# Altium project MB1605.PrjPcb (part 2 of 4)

## Sheet Power_PMIC.SchDoc: Power PMIC
size A3; Date: Not used; ApprovedBy: Not used; CheckedBy: Not used; Author: Not used; CompanyName: STMicroelectronics; DrawnBy: Not used; Engineer: Not used; Organization: Not used; Address1: Not used; Address2: Not used; Address3: Not used; Address4: Not used; DocumentNumber: Not used; Revision: Not used; SheetNumber: 4; SheetTotal: 18
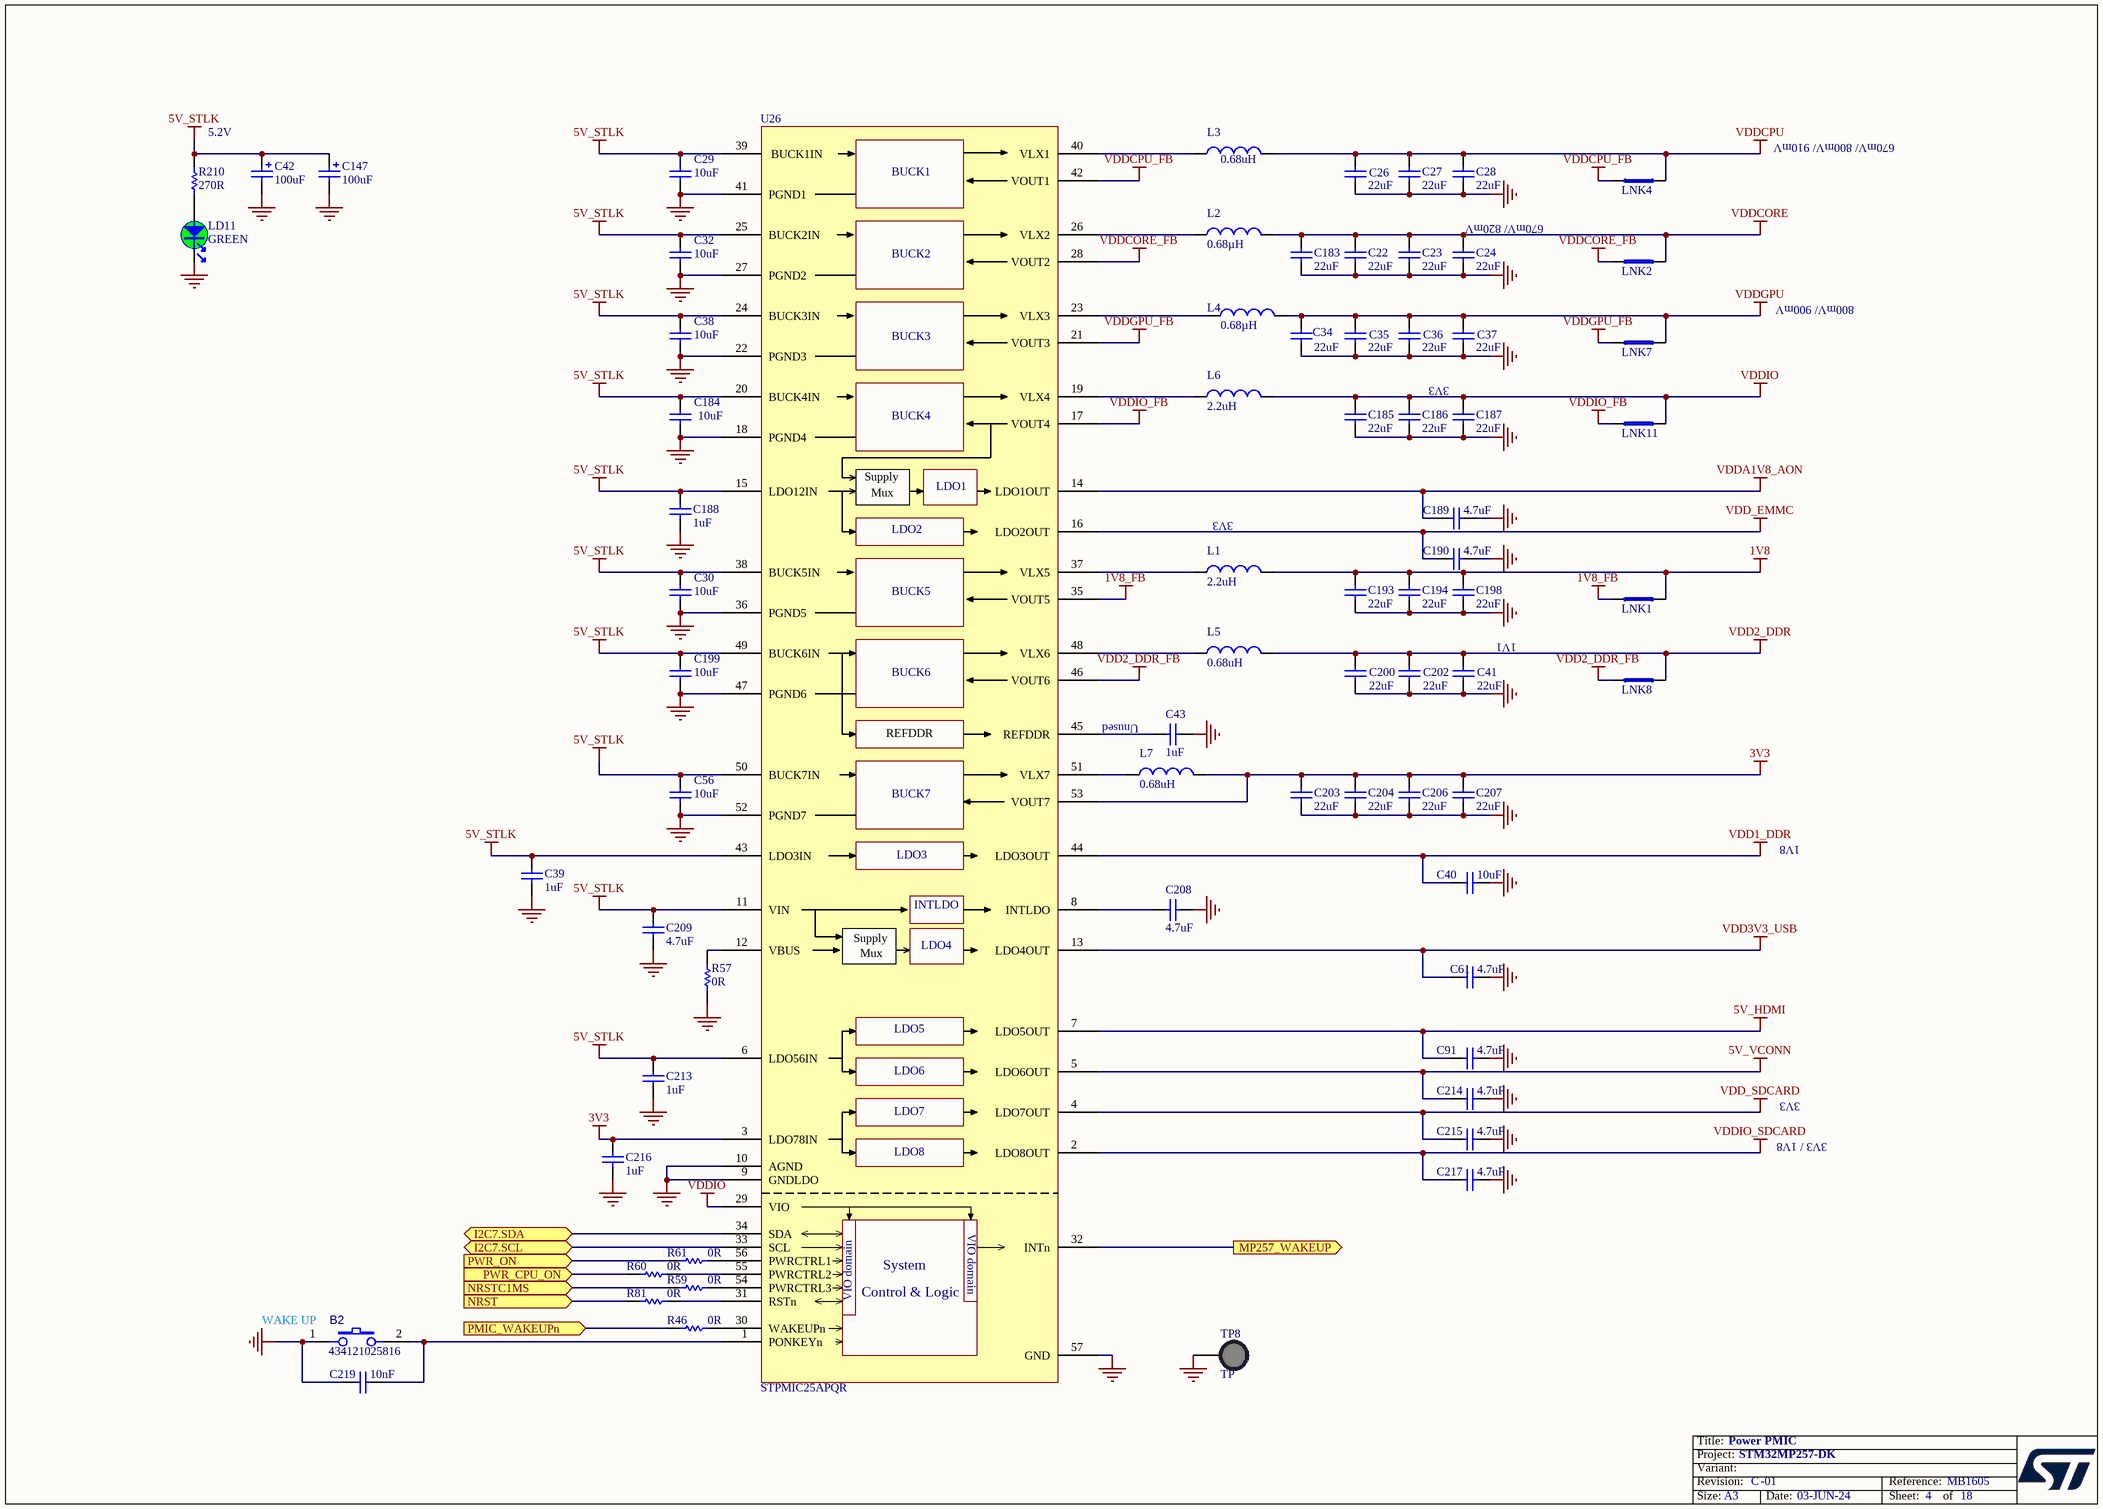
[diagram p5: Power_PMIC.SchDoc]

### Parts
B2  value 434121025816  [SWI_WE_434121025816]  (hidden comment: SW_PUSH_SMD_2P)
C22  value 22uF  [C0603]  (hidden comment: Capacitor)
C23  value 22uF  [C0603]  (hidden comment: Capacitor)
C24  value 22uF  [C0603]  (hidden comment: Capacitor)
C26  value 22uF  [C0603]  (hidden comment: Capacitor)
C27  value 22uF  [C0603]  (hidden comment: Capacitor)
C28  value 22uF  [C0603]  (hidden comment: Capacitor)
C29  value 10uF  [C0603]  (hidden comment: Capacitor)
C30  value 10uF  [C0603]  (hidden comment: Capacitor)
C32  value 10uF  [C0603]  (hidden comment: Capacitor)
C34  value 22uF  [C0603]  (hidden comment: Capacitor)
C35  value 22uF  [C0603]  (hidden comment: Capacitor)
C36  value 22uF  [C0603]  (hidden comment: Capacitor)
C37  value 22uF  [C0603]  (hidden comment: Capacitor)
C38  value 10uF  [C0603]  (hidden comment: Capacitor)
C39  value 1uF  [C0402]  (hidden comment: Capacitor)
C40  value 10uF  [C0402]  (hidden comment: Capacitor)
C41  value 22uF  [C0603]  (hidden comment: Capacitor)
C42  value 100uF  [CPOL_TCJ-B_1210_H210]  (hidden comment: Cap_POL_TANA)
C43  value 1uF  [C0402]  (hidden comment: Capacitor)
C56  value 10uF  [C0603]  (hidden comment: Capacitor)
C61  value 4.7uF  [C0402]  (hidden comment: Capacitor)
C91  value 4.7uF  [C0402]  (hidden comment: Capacitor)
C147  value 100uF  [CPOL_TCJ-B_1210_H210]  (hidden comment: Cap_POL_TANA)
C183  value 22uF  [C0603]  (hidden comment: Capacitor)
C184  value 10uF  [C0603]  (hidden comment: Capacitor)
C185  value 22uF  [C0805]  (hidden comment: Capacitor)
C186  value 22uF  [C0805]  (hidden comment: Capacitor)
C187  value 22uF  [C0805]  (hidden comment: Capacitor)
C188  value 1uF  [C0402]  (hidden comment: Capacitor)
C189  value 4.7uF  [C0402]  (hidden comment: Capacitor)
C190  value 4.7uF  [C0402]  (hidden comment: Capacitor)
C193  value 22uF  [C0805]  (hidden comment: Capacitor)
C194  value 22uF  [C0805]  (hidden comment: Capacitor)
C198  value 22uF  [C0805]  (hidden comment: Capacitor)
C199  value 10uF  [C0603]  (hidden comment: Capacitor)
C200  value 22uF  [C0603]  (hidden comment: Capacitor)
C202  value 22uF  [C0603]  (hidden comment: Capacitor)
C203  value 22uF  [C0805]  (hidden comment: Capacitor)
C204  value 22uF  [C0805]  (hidden comment: Capacitor)
C206  value 22uF  [C0805]  (hidden comment: Capacitor)
C207  value 22uF  [C0805]  (hidden comment: Capacitor)
C208  value 4.7uF  [C0402]  (hidden comment: Capacitor)
C209  value 4.7uF  [C0402]  (hidden comment: Capacitor)
C213  value 1uF  [C0402]  (hidden comment: Capacitor)
C214  value 4.7uF  [C0402]  (hidden comment: Capacitor)
C215  value 4.7uF  [C0402]  (hidden comment: Capacitor)
C216  value 1uF  [C0402]  (hidden comment: Capacitor)
C217  value 4.7uF  [C0402]  (hidden comment: Capacitor)
C219  value 10nF  [C0402]  (hidden comment: Capacitor)
L1  value 2.2uH  [IND_2016_MURATA_LQM2MPN2R2NG0]  (hidden comment: Inductor)
L2  value 0.68µH  [IND_2520_TOKO_DFE252012P]  (hidden comment: Inductor)
L3  value 0.68uH  [IND_2016_MURATA_LQM2MPN2R2NG0]  (hidden comment: Inductor)
L4  value 0.68µH  [IND_2520_TOKO_DFE252012P]  (hidden comment: Inductor)
L5  value 0.68uH  [IND_2016_MURATA_LQM2MPN2R2NG0]  (hidden comment: Inductor)
L6  value 2.2uH  [IND_2016_MURATA_LQM2MPN2R2NG0]  (hidden comment: Inductor)
L7  value 0.68uH  [IND_2016_MURATA_LQM2MPN2R2NG0]  (hidden comment: Inductor)
LD11  value GREEN  [LED_0603_OSRAM_LG-Q396-PS-35_GREEN_1A2K_H0P4]  (hidden comment: LED_green)
LNK1  link_200  [LINK200]  (value not drawn)  (no BOM)
LNK2  link_200  [LINK200]  (value not drawn)  (no BOM)
LNK4  link_200  [LINK200]  (value not drawn)  (no BOM)
LNK7  link_200  [LINK200]  (value not drawn)  (no BOM)
LNK8  link_200  [LINK200]  (value not drawn)  (no BOM)
LNK11  link_200  [LINK200]  (value not drawn)  (no BOM)
R46  value 0R  [R0402]
R57  value 0R  [R0402]
R59  value 0R  [R0402]
R60  value 0R  [R0402]
R61  value 0R  [R0402]
R81  value 0R  [R0402]
R210  value 270R  [R0402]  (hidden comment: Resistor)
TP8  value TP  [TP_PTH-1P02MM_TEST-TERMINAL_RS_101-2391_BLACK]  (hidden comment: Test_pin_conn_black)
U26  STPMIC25APQR  [ICC_QFN56-EPAD_6P5X6P5_P040]

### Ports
I2C7.SCL (bidir), I2C7.SDA (bidir), MP257_WAKEUP (out), NRST (in), NRSTC1MS (in), PMIC_WAKEUPn (in), PWR_CPU_ON (in), PWR_ON (in)

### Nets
1V8: C193.2 C194.2 C198.2 L1.2 LNK1.2
1V8_FB: LNK1.1 U26.35(VOUT5)
3V3: C203.2 C204.2 C206.2 C207.2 C216.2 L7.2 U26.3(LDO78IN) U26.53(VOUT7)
5V_HDMI: C91.1 U26.7(LDO5OUT)
5V_STLK: C29.2 C30.2 C32.2 C38.2 C39.2 C42.1 C56.2 C147.1 C184.2 C188.2 C199.2 C209.2 C213.2 R210.1 U26.6(LDO56IN) U26.11(VIN) U26.15(LDO12IN) U26.20(BUCK4IN) U26.24(BUCK3IN) U26.25(BUCK2IN) U26.38(BUCK5IN) U26.39(BUCK1IN) U26.43(LDO3IN) U26.49(BUCK6IN) U26.50(BUCK7IN)
5V_VCONN: C214.1 U26.5(LDO6OUT)
GND: B2.1 C22.1 C23.1 C24.1 C26.1 C27.1 C28.1 C29.1 C30.1 C32.1 C34.1 C35.1 C36.1 C37.1 C38.1 C39.1 C40.1 C41.1 C42.2 C43.1 C56.1 C61.1 C91.2 C147.2 C183.1 C184.1 C185.1 C186.1 C187.1 C188.1 C189.1 C190.2 C193.1 C194.1 C198.1 C199.1 C200.1 C202.1 C203.1 C204.1 C206.1 C207.1 C208.2 C209.1 C213.1 C214.2 C215.2 C216.1 C217.2 C219.1 LD11.2 R57.1 TP8.1 U26.9(GNDLDO) U26.10(AGND) U26.18(PGND4) U26.22(PGND3) U26.27(PGND2) U26.36(PGND5) U26.41(PGND1) U26.47(PGND6) U26.52(PGND7) U26.57(GND)
VDD1_DDR: C40.2 U26.44(LDO3OUT)
VDD2_DDR: C41.2 C200.2 C202.2 L5.2 LNK8.2
VDD2_DDR_FB: LNK8.1 U26.46(VOUT6)
VDD3V3_USB: C61.2 U26.13(LDO4OUT)
VDD_EMMC: C190.1 U26.16(LDO2OUT)
VDD_SDCARD: C215.1 U26.4(LDO7OUT)
VDDA1V8_AON: C189.2 U26.14(LDO1OUT)
VDDCORE: C22.2 C23.2 C24.2 C183.2 L2.2 LNK2.2
VDDCORE_FB: LNK2.1 U26.28(VOUT2)
VDDCPU: C26.2 C27.2 C28.2 L3.2 LNK4.1
VDDCPU_FB: LNK4.2 U26.42(VOUT1)
VDDGPU: C34.2 C35.2 C36.2 C37.2 L4.2 LNK7.2
VDDGPU_FB: LNK7.1 U26.21(VOUT3)
VDDIO: C185.2 C186.2 C187.2 L6.2 LNK11.2 U26.29(VIO)
VDDIO_FB: LNK11.1 U26.17(VOUT4)
VDDIO_SDCARD: C217.1 U26.2(LDO8OUT)
I2C7.SCL: U26.33(SCL) ; port I2C7.SCL
I2C7.SDA: U26.34(SDA) ; port I2C7.SDA
MP257_WAKEUP: U26.32(INTn) ; port MP257_WAKEUP
NRST: R81.1 ; port NRST
NRSTC1MS: R59.1 ; port NRSTC1MS
PMIC_WAKEUPn: R46.1 ; port PMIC_WAKEUPn
PWR_CPU_ON: R60.1 ; port PWR_CPU_ON
PWR_ON: R61.1 ; port PWR_ON
NetB2_2: B2.2 C219.2 U26.1(PONKEYn)
NetC43_2: C43.2 U26.45(REFDDR)
NetC208_1: C208.1 U26.8(INTLDO)
NetL1_1: L1.1 U26.37(VLX5)
NetL2_1: L2.1 U26.26(VLX2)
NetL3_1: L3.1 U26.40(VLX1)
NetL4_1: L4.1 U26.23(VLX3)
NetL5_1: L5.1 U26.48(VLX6)
NetL6_1: L6.1 U26.19(VLX4)
NetL7_1: L7.1 U26.51(VLX7)
NetLD11_1: LD11.1 R210.2
NetR46_2: R46.2 U26.30(WAKEUPn)
NetR57_2: R57.2 U26.12(VBUS)
NetR59_2: R59.2 U26.54(PWRCTRL3)
NetR60_2: R60.2 U26.55(PWRCTRL2)
NetR61_2: R61.2 U26.56(PWRCTRL1)
NetR81_2: R81.2 U26.31(RSTn)

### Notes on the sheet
- 5.2V
- 670mV/ 800mV/ 910mV
- (near C24) 670mV/ 820mV
- 800mV/ 900mV
- 3V3
- (near L1) 3V3
- 1V1
- Unused
- 1V8
- 3V3 / 1V8
- (near B2) WAKE UP

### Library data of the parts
B2 = MCD-03492: Switch tactile, SPST-NO, 50mA, 12V, 6x3.8mm; Part_Type: Misc; Part_Preference: Recommended; Manufacturer: WURTH ELEKTRONIC; Component_Country_Of_Origin: China°; ShowFields: YES; ID: 5608
C22-C24 C26 C34-C37 C41 C200 C202 = MCD-00100: Capacitor, MLCC, 22uF, 6V3, X5R, +/-20%, 0603, T=0,8mm; Manufacturer_Part_Number: GRM188R60J226MEA0J; Manufacturer: MURATA; Part_Preference: Recommended; Component_Country_Of_Origin: Japan; ID: 2766; ShowFields: YES
C27 C28 C183 = MCD-00100: Capacitor, MLCC, 22uF, 6V3, X5R, +/-20%, 0603, T=0,8mm; Part_Preference: Recommended; Manufacturer: MURATA; Manufacturer_Part_Number: GRM188R60J226MEA0J; Component_Country_Of_Origin: Japan; ID: 2766; ShowFields: YES
C29 C30 C32 C38 C56 C184 C199 = MCD-00099: Capacitor, MLCC, 10uF, 10V, X5R, +/-10%, 0603, T=0,8mm; Manufacturer_Part_Number: GRM188R61A106KE69D; Manufacturer: MURATA; Part_Preference: Recommended; Order_Code_RS: 170-6168; Component_Country_Of_Origin: Japan; ID: 2770; ShowFields: YES
C39 C43 C188 C213 C216 = MCD-00095: Capacitor, MLCC, 1uF, 25V, X5R, +/-10%, 0402, T=0.5mm; Part_Preference: Recommended; Manufacturer: MURATA; Manufacturer_Part_Number: GRM155R61E105KA12; Order_Code_RS: 846-7287; Component_Country_Of_Origin: Japan; ShowFields: YES; ID: 2772
C40 = MCD-03140: Capacitor, MLCC, 10uF, 6.3V, X5R, +/-20%, 0402, T=0.5mm; Part_Preference: Recommended; Manufacturer: MURATA; Manufacturer_Part_Number: GRM155R60J106ME05D; ShowFields: YES; ID: 5256; Component_Country_Of_Origin: China, Japan
C42 C147 = MCD-01796: Capacitor, Tantalum, 100uF, 6V3, 40mR, +/-20%,  Type_B (3528 metric), T=1.9mm; Part_Preference: Recommended; Manufacturer: AVX; Manufacturer_Part_Number: TCJB107M006R0040; Component_Country_Of_Origin: Lanskroun; ShowFields: YES; ID: 3896
C61 C91 C189 C190 C208 C209 C214 C215 C217 = MCD-01356: Capacitor, MLCC, 4.7uF, 6V3, X5R, +/-20%, 0402, T=0.5mm; Manufacturer_Part_Number: GRM155R60J475ME47; Manufacturer: MURATA; Part_Preference: Recommended; Order_Code_RS: 814-5230; Component_Country_Of_Origin: Japan; ShowFields: YES; ID: 3456
C185-C187 C193 C194 C198 C203 C204 C206 C207 = MCD-03139: Capacitor, MLCC, 22uF, 10V, X5R, +/-20%, 0805, T=1,25mm; Part_Preference: Recommended; Manufacturer: MURATA; Manufacturer_Part_Number: GRM21BR61A226ME51L; ShowFields: YES; ID: 5255; Component_Country_Of_Origin: China, Japan
C219 = MCD-02198: Capacitor, MLCC, 10nF, 50V, X7R, +/-10%, 0402, T=0.5mm; Manufacturer_Part_Number: CC0402KRX7R9BB103; Manufacturer: YAGEO; Part_Preference: Recommended; Order_Code_RS: 6169644; Component_Country_Of_Origin: China; ShowFields: YES; ID: 4298
L1 L6 = MCD-03143: Inductor, 2.2uH, +/-20%, Itemp= 1700mA, Isat= 2400mA, 0R140, 0806, T=1mm; Part_Preference: Recommended; Manufacturer: MURATA; Manufacturer_Part_Number: DFE201610E-2R2M=P2; ShowFields: YES; ID: 5259; Component_Country_Of_Origin: Vietnam
L2 L4 = MCD-03142: Inductor, 0.68uH, +/-20%, Itemp= 3900mA, Isat= 5400mA, 0R031, 1008, T=1.2mm; Part_Preference: Recommended; Manufacturer: MURATA; Manufacturer_Part_Number: DFE252012F-R68M=P2; ShowFields: YES; ID: 5258; Component_Country_Of_Origin: Vietnam
L3 L5 L7 = MCD-03141: Inductor, 0.68uH, +/-20%, Itemp= 3100mA, Isat= 4300mA, 0R043, 0806, T=1mm; Part_Preference: Recommended; Manufacturer: MURATA; Manufacturer_Part_Number: DFE201610E-R68M=P2; ShowFields: YES; ID: 5257; Component_Country_Of_Origin: Vietnam
LD11 = MCD-00588: LED Green, 0603 SMD, Forward Voltage Typ=2V, Max=2.5V; Part_Type: Display; Manufacturer_Part_Number: LG Q396-PS-35; Manufacturer: OSRAM OPTO SEMICONDUCTORS; Alternate_Manufacturer_Part_Number: VLMTG1300-GS08; Alternate_Manufacturer: VISHAY SEMICONDUCTOR OPTO DIVISION; Alternate_Internal_Part_Number: MCD-02400; Part_Preference: Recommended; Provided_By: SUBCO; Component_Country_Of_Origin: Unknown; ID: 3155; ShowFields: YES
LNK1 LNK2 LNK4 LNK7 LNK8 LNK11 = MCD-02777: Track link on PCB 200um width for layout routing; Part_Preference: Recommended; Part_Type: Misc; ID: 4889; ShowFields: YES
R46 R57 R59-R61 R81 = MCD-00052: Resistor,0R,0402,5%,1/16W; Manufacturer_Part_Number: RC0402JR-070RL; Manufacturer: YAGEO; Part_Preference: Recommended; ECCN_US: EAR99; ECCN_EU: NEC; Provided_By: SUBCO; Initial_Board_Reference: mb1274; Order_Code_RS: 618-5804; Component_Country_Of_Origin: China; ID: 2540; ShowFields: YES
R210 = MCD-00441: Resistor,270R,0402,1%,1/16W; Manufacturer_Part_Number: RC0402FR-07270RL; Manufacturer: YAGEO; Part_Preference: Recommended; Provided_By: SUBCO; ECCN_US: EAR99; ECCN_EU: NEC; Component_Country_Of_Origin: China; ID: 2838; ShowFields: YES
TP8 = MCD-00713: Vero Technologies 1.02mm Black Terminal Post; Part_Type: Misc; Manufacturer_Part_Number: 20-2137; Part_Preference: Recommended; Order_Code_RS: 101-2391; Component_Country_Of_Origin: United Kingdom; ID: 3032; ShowFields: YES
U26 = MCD-03000: STPMIC2; Part_Type: IC; Part_Preference: Recommended; Manufacturer: STMICROELECTRONICS; Component_Country_Of_Origin: Unknown; ShowFields: YES; ID: 5116

## Sheet Power_MPU.SchDoc: Power MPU
size A3; Date: Not used; ApprovedBy: Not used; CheckedBy: Not used; Author: Not used; CompanyName: STMicroelectronics; DrawnBy: Not used; Engineer: Not used; Organization: Not used; Address1: Not used; Address2: Not used; Address3: Not used; Address4: Not used; DocumentNumber: Not used; Revision: Not used; SheetNumber: 5; SheetTotal: 18
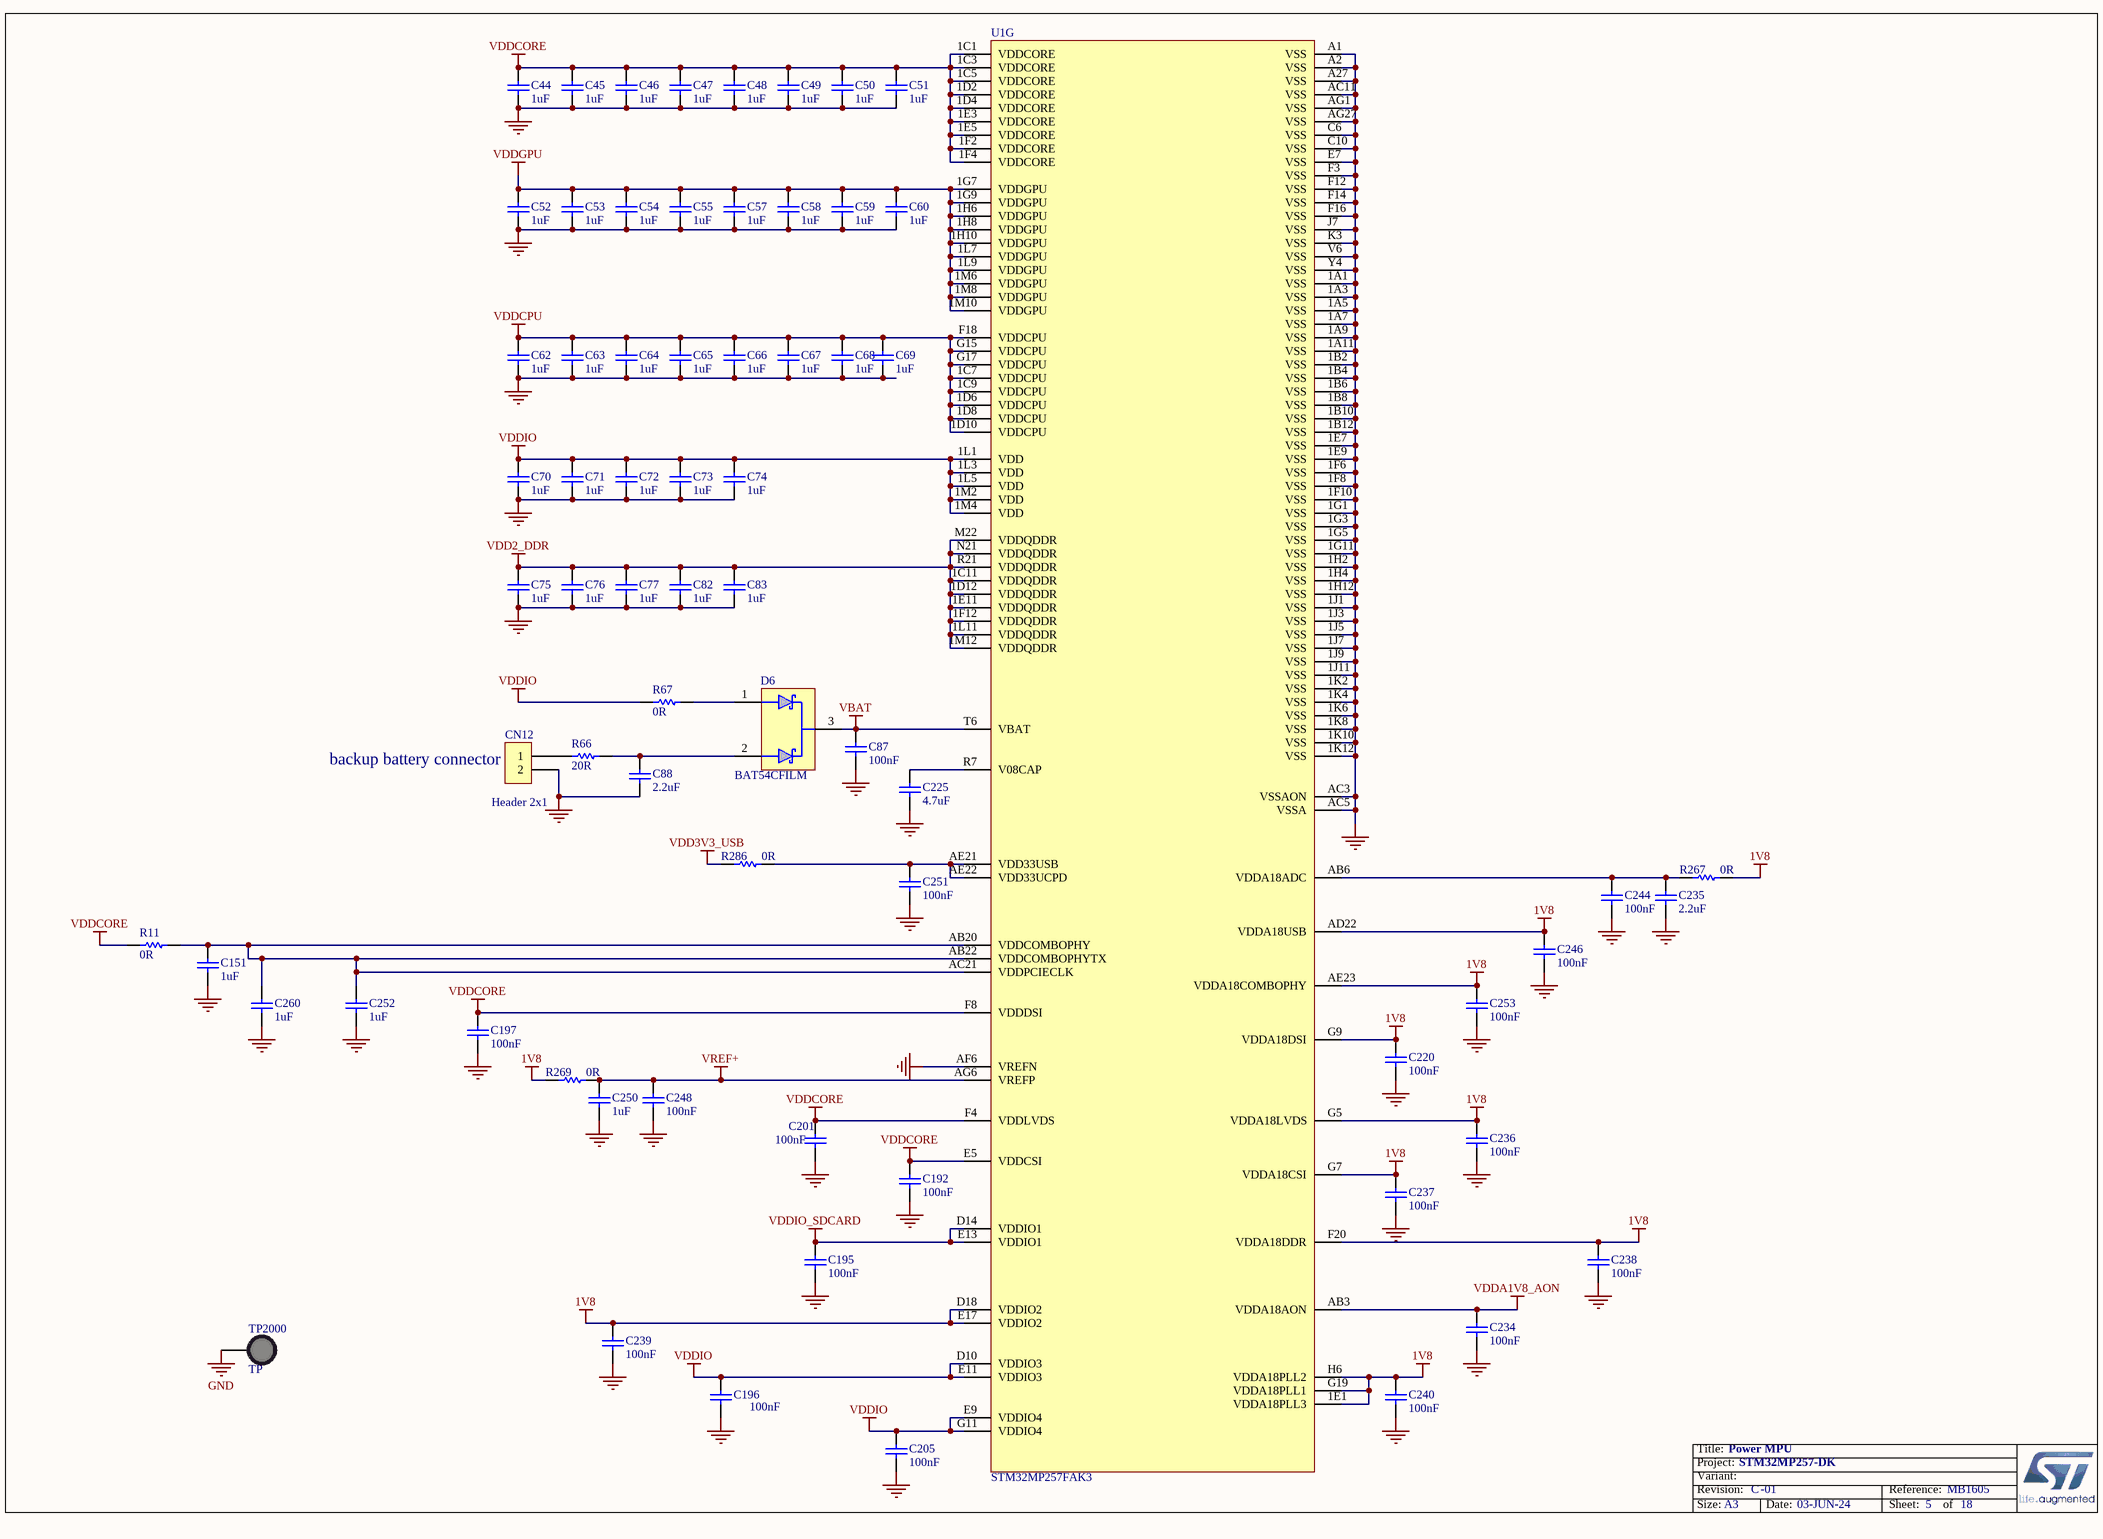
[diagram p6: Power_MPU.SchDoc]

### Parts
C44  1uF  [C0201_MURATA_GRM033_H0P3]
C45  1uF  [C0201_MURATA_GRM033_H0P3]
C46  1uF  [C0201_MURATA_GRM033_H0P3]
C47  1uF  [C0201_MURATA_GRM033_H0P3]
C48  1uF  [C0201_MURATA_GRM033_H0P3]
C49  1uF  [C0201_MURATA_GRM033_H0P3]
C50  1uF  [C0201_MURATA_GRM033_H0P3]
C51  1uF  [C0201_MURATA_GRM033_H0P3]
C52  1uF  [C0201_MURATA_GRM033_H0P3]
C53  1uF  [C0201_MURATA_GRM033_H0P3]
C54  1uF  [C0201_MURATA_GRM033_H0P3]
C55  1uF  [C0201_MURATA_GRM033_H0P3]
C57  1uF  [C0201_MURATA_GRM033_H0P3]
C58  1uF  [C0201_MURATA_GRM033_H0P3]
C59  1uF  [C0201_MURATA_GRM033_H0P3]
C60  1uF  [C0201_MURATA_GRM033_H0P3]
C62  1uF  [C0201_MURATA_GRM033_H0P3]
C63  1uF  [C0201_MURATA_GRM033_H0P3]
C64  1uF  [C0201_MURATA_GRM033_H0P3]
C65  1uF  [C0201_MURATA_GRM033_H0P3]
C66  1uF  [C0201_MURATA_GRM033_H0P3]
C67  1uF  [C0201_MURATA_GRM033_H0P3]
C68  1uF  [C0201_MURATA_GRM033_H0P3]
C69  1uF  [C0201_MURATA_GRM033_H0P3]
C70  1uF  [C0201_MURATA_GRM033_H0P3]
C71  1uF  [C0201_MURATA_GRM033_H0P3]
C72  1uF  [C0201_MURATA_GRM033_H0P3]
C73  1uF  [C0201_MURATA_GRM033_H0P3]
C74  1uF  [C0201_MURATA_GRM033_H0P3]
C75  1uF  [C0201_MURATA_GRM033_H0P3]
C76  1uF  [C0201_MURATA_GRM033_H0P3]
C77  1uF  [C0201_MURATA_GRM033_H0P3]
C82  1uF  [C0201_MURATA_GRM033_H0P3]
C83  1uF  [C0201_MURATA_GRM033_H0P3]
C87  value 100nF  [C0402]
C88  value 2.2uF  [C0402]  (hidden comment: Capacitor)
C151  value 1uF  [C0201_MURATA_GRM033_H0P3]  (hidden comment: Capacitor)
C192  value 100nF  [C0201_MURATA_GRM033_H0P3]  (hidden comment: Capacitor)
C195  value 100nF  [C0201_MURATA_GRM033_H0P3]  (hidden comment: Capacitor)
C196  value 100nF  [C0201_MURATA_GRM033_H0P3]  (hidden comment: Capacitor)
C197  value 100nF  [C0201_MURATA_GRM033_H0P3]  (hidden comment: Capacitor)
C201  value 100nF  [C0201_MURATA_GRM033_H0P3]  (hidden comment: Capacitor)
C205  value 100nF  [C0201_MURATA_GRM033_H0P3]  (hidden comment: Capacitor)
C220  value 100nF  [C0201_MURATA_GRM033_H0P3]  (hidden comment: Capacitor)
C225  value 4.7uF  [C0201_H0P5]  (hidden comment: Capacitor)
C234  value 100nF  [C0201_MURATA_GRM033_H0P3]  (hidden comment: Capacitor)
C235  value 2.2uF  [C0201_H0P5]  (hidden comment: Capacitor)
C236  value 100nF  [C0201_MURATA_GRM033_H0P3]  (hidden comment: Capacitor)
C237  value 100nF  [C0201_MURATA_GRM033_H0P3]  (hidden comment: Capacitor)
C238  value 100nF  [C0201_MURATA_GRM033_H0P3]  (hidden comment: Capacitor)
C239  value 100nF  [C0201_MURATA_GRM033_H0P3]  (hidden comment: Capacitor)
C240  value 100nF  [C0201_MURATA_GRM033_H0P3]  (hidden comment: Capacitor)
C244  value 100nF  [C0201_MURATA_GRM033_H0P3]  (hidden comment: Capacitor)
C246  value 100nF  [C0201_MURATA_GRM033_H0P3]  (hidden comment: Capacitor)
C248  value 100nF  [C0201_MURATA_GRM033_H0P3]  (hidden comment: Capacitor)
C250  value 1uF  [C0201_MURATA_GRM033_H0P3]  (hidden comment: Capacitor)
C251  value 100nF  [C0201_MURATA_GRM033_H0P3]  (hidden comment: Capacitor)
C252  value 1uF  [C0201_MURATA_GRM033_H0P3]  (hidden comment: Capacitor)
C253  value 100nF  [C0201_MURATA_GRM033_H0P3]  (hidden comment: Capacitor)
C260  value 1uF  [C0201_MURATA_GRM033_H0P3]  (hidden comment: Capacitor)
CN12  value Header 2x1  [CON_MOLEX_53047-0210]
D6  value BAT54CFILM  [DIO_SOT23]  (hidden comment: DIODE_3P_DUAL_COMMON_CATHODE)
R11  value 0R  [R0603]  (hidden comment: Resistor)
R66  value 20R  [R0402]  (hidden comment: Resistor)
R67  value 0R  [R0402]  (hidden comment: Resistor)
R267  value 0R  [R0402]
R269  value 0R  [R0402]
R286  value 0R  [R0402]
TP2000  value TP  [TP_PTH-1P02MM_TEST-TERMINAL_RS_101-2391_BLACK]  (hidden comment: Test_pin_conn_black)
U1  STM32MP257FAK3  [ICC_TFBGA424_14X14_P050_H1P20_CODE-B0A2]  (part G of 9)

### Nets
1V8: C220.2 C236.2 C237.2 C238.2 C239.2 C240.2 C246.2 C253.2 R267.2 R269.1 U1.1E1(VDDA18PLL3) U1.AD22(VDDA18USB) U1.AE23(VDDA18COMBOPHY) U1.D18(VDDIO2) U1.E17(VDDIO2) U1.F20(VDDA18DDR) U1.G5(VDDA18LVDS) U1.G7(VDDA18CSI) U1.G9(VDDA18DSI) U1.G19(VDDA18PLL1) U1.H6(VDDA18PLL2)
GND: C44.2 C45.1 C46.1 C47.2 C48.1 C49.1 C50.1 C51.1 C52.1 C53.1 C54.1 C55.1 C57.1 C58.1 C59.1 C60.1 C62.2 C63.1 C64.1 C65.2 C66.1 C67.1 C68.1 C69.1 C70.2 C71.1 C72.1 C73.2 C74.1 C75.1 C76.1 C77.2 C82.1 C83.1 C87.1 C88.1 C151.1 C192.1 C195.1 C196.1 C197.1 C201.1 C205.1 C220.1 C225.1 C234.1 C235.1 C236.1 C237.1 C238.1 C239.1 C240.1 C244.1 C246.1 C248.1 C250.1 C251.1 C252.1 C253.1 C260.1 CN12.2 TP2000.1 U1.1A1(VSS) U1.1A3(VSS) U1.1A5(VSS) U1.1A7(VSS) U1.1A9(VSS) U1.1A11(VSS) U1.1B2(VSS) U1.1B4(VSS) U1.1B6(VSS) U1.1B8(VSS) U1.1B10(VSS) U1.1B12(VSS) U1.1E7(VSS) U1.1E9(VSS) U1.1F6(VSS) U1.1F8(VSS) U1.1F10(VSS) U1.1G1(VSS) U1.1G3(VSS) U1.1G5(VSS) U1.1G11(VSS) U1.1H2(VSS) U1.1H4(VSS) U1.1H12(VSS) U1.1J1(VSS) U1.1J3(VSS) U1.1J5(VSS) U1.1J7(VSS) U1.1J9(VSS) U1.1J11(VSS) U1.1K2(VSS) U1.1K4(VSS) U1.1K6(VSS) U1.1K8(VSS) U1.1K10(VSS) U1.1K12(VSS) U1.A1(VSS) U1.A2(VSS) U1.A27(VSS) U1.AC3(VSSAON) U1.AC5(VSSA) U1.AC11(VSS) U1.AF6(VREFN) U1.AG1(VSS) U1.AG27(VSS) U1.C6(VSS) U1.C10(VSS) U1.E7(VSS) U1.F3(VSS) U1.F12(VSS) U1.F14(VSS) U1.F16(VSS) U1.J7(VSS) U1.K3(VSS) U1.V6(VSS) U1.Y4(VSS)
VBAT: C87.2 D6.3 U1.T6(VBAT)
VDD2_DDR: C75.2 C76.2 C77.1 C82.2 C83.2 U1.1C11(VDDQDDR) U1.1D12(VDDQDDR) U1.1E11(VDDQDDR) U1.1F12(VDDQDDR) U1.1L11(VDDQDDR) U1.1M12(VDDQDDR) U1.M22(VDDQDDR) U1.N21(VDDQDDR) U1.R21(VDDQDDR)
VDD3V3_USB: R286.1
VDDA1V8_AON: C234.2 U1.AB3(VDDA18AON)
VDDCORE: C44.1 C45.2 C46.2 C47.1 C48.2 C49.2 C50.2 C51.2 C192.2 C197.2 C201.2 R11.1 U1.1C1(VDDCORE) U1.1C3(VDDCORE) U1.1C5(VDDCORE) U1.1D2(VDDCORE) U1.1D4(VDDCORE) U1.1E3(VDDCORE) U1.1E5(VDDCORE) U1.1F2(VDDCORE) U1.1F4(VDDCORE) U1.E5(VDDCSI) U1.F4(VDDLVDS) U1.F8(VDDDSI)
VDDCPU: C62.1 C63.2 C64.2 C65.1 C66.2 C67.2 C68.2 C69.2 U1.1C7(VDDCPU) U1.1C9(VDDCPU) U1.1D6(VDDCPU) U1.1D8(VDDCPU) U1.1D10(VDDCPU) U1.F18(VDDCPU) U1.G15(VDDCPU) U1.G17(VDDCPU)
VDDGPU: C52.2 C53.2 C54.2 C55.2 C57.2 C58.2 C59.2 C60.2 U1.1G7(VDDGPU) U1.1G9(VDDGPU) U1.1H6(VDDGPU) U1.1H8(VDDGPU) U1.1H10(VDDGPU) U1.1L7(VDDGPU) U1.1L9(VDDGPU) U1.1M6(VDDGPU) U1.1M8(VDDGPU) U1.1M10(VDDGPU)
VDDIO: C70.1 C71.2 C72.2 C73.1 C74.2 C196.2 C205.2 R67.2 U1.1L1(VDD) U1.1L3(VDD) U1.1L5(VDD) U1.1M2(VDD) U1.1M4(VDD) U1.D10(VDDIO3) U1.E9(VDDIO4) U1.E11(VDDIO3) U1.G11(VDDIO4)
VDDIO_SDCARD: C195.2 U1.D14(VDDIO1) U1.E13(VDDIO1)
VREF+: C248.2 C250.2 R269.2 U1.AG6(VREFP)
NetC88_2: C88.2 D6.2 R66.2
NetC151_2: C151.2 C252.2 C260.2 R11.2 U1.AB20(VDDCOMBOPHY) U1.AB22(VDDCOMBOPHYTX) U1.AC21(VDDPCIECLK)
NetC225_2: C225.2 U1.R7(V08CAP)
NetC235_2: C235.2 C244.2 R267.1 U1.AB6(VDDA18ADC)
NetC251_2: C251.2 R286.2 U1.AE21(VDD33USB) U1.AE22(VDD33UCPD)
NetCN12_1: CN12.1 R66.1
NetD6_1: D6.1 R67.1

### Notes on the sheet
- (near CN12) backup battery connector

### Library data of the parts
C44-C55 C57-C60 C62-C77 C82 C83 = MCD-02377: Capacitor, MLCC, 1uF, 6.3V, X5R, +/-20%, 0201, T=0,3mm; Part_Preference: Recommended; Manufacturer: MURATA; Manufacturer_Part_Number: GRM033R60J105MEA2; Order_Code_RS: 820-0643; Component_Country_Of_Origin: Japan; ShowFields: YES; ID: 4483
C87 = MCD-00006: Capacitor,100nF,16V,X7R,10%,0402; Manufacturer_Part_Number: CC0402KRX7R7BB104; Manufacturer: YAGEO; Alternate_Manufacturer: MURATA; Alternate_Manufacturer_Part_Number: GCM155R71C104KA55D; Part_Preference: Recommended; Partial_Alternate_Internal_Part_Number: MCD-03299; Provided_By: SUBCO; Initial_Board_Reference: MB1274; Order_Code_RS: 616-9701; Component_Country_Of_Origin: China; ID: 2474; ShowFields: YES; Alternate_EMS: M
C88 = MCD-01823: Capacitor, MLCC, 2.2uF, 6V3, X5R,+/-10%, 0402, T=0.5mm; Part_Preference: Recommended; Manufacturer: MURATA; Manufacturer_Part_Number: GRM155R60J225KE95D; Order_Code_RS: 172-6478; Component_Country_Of_Origin: Japan; ID: 3923; ShowFields: YES
C151 C250 C252 C260 = MCD-02377: Capacitor, MLCC, 1uF, 6.3V, X5R, +/-20%, 0201, T=0,3mm; Manufacturer_Part_Number: GRM033R60J105MEA2; Manufacturer: MURATA; Part_Preference: Recommended; Order_Code_RS: 820-0643; Component_Country_Of_Origin: Japan; ID: 4483; ShowFields: YES
C192 C195-C197 C201 C205 C220 C234 C236-C240 C244 C246 C248 C251 C253 = MCD-01535: Capacitor, MLCC,100nF, 10V, X7R, +/-10%, 0201, T=0.3mm; Part_Preference: Recommended; Manufacturer: MURATA; Manufacturer_Part_Number: GRM033R61A104KE15; Order_Code_RS: 790-2742; Component_Country_Of_Origin: Japan; ID: 3635; ShowFields: YES
C225 = MCD-01534: Capacitor, MLCC, 4,7uF, 6V3, X5R, +/-20%, 0201, T=0.5mm; Part_Preference: Recommended; Manufacturer: MURATA; Manufacturer_Part_Number: GRM035R60J475ME15; Component_Country_Of_Origin: Japan; ID: 3634; ShowFields: YES
C235 = MCD-02235: Capacitor, MLCC, 2.2uF, 10V, X5R,+/-10%, 0201, T=0.5mm; Part_Preference: Recommended; Manufacturer: MURATA; Manufacturer_Part_Number: GRM033R61A225KE47D; Order_Code_RS: NA; Component_Country_Of_Origin: Japan; ShowFields: YES; ID: 4335
CN12 = MCD-00655: Header 2 circuits, 1.25mm Pitch ,  Vertical, with Friction Lock; Part_Type: Connector; Manufacturer_Part_Number: 53047-0210; Manufacturer: MOLEX; BMS_Part_Number: 9083002; Part_Preference: Recommended; Provided_By: SUBCO; Initial_Board_Reference: MB1272; Order_Code_RS: 279-9213; Component_Country_Of_Origin: Unknown; ID: 3091; ShowFields: YES
D6 = MCD-03280: Diode, Schottky, Dual Common Cathode, 0V3, 300mA, 40V, SOT-23; Part_Preference: Recommended; Manufacturer: STMICROELECTRONICS; Full_Alternate_Internal_Part_Number: BAT54C+, BAT54CLT1G, BAT54C-7-F, BAT54C,215; Order_code_RS: 795-8397; Component_Country_Of_Origin: China; ShowFields: YES; ID: 5396
R11 = MCD-00056: Resistor, 0R, 0603, +/-5%, 1/10W; Part_Preference: Recommended; Manufacturer: YAGEO; Manufacturer_Part_Number: RC0603JR-070RL; Component_Country_Of_Origin: China; ShowFields: YES; ID: 2536
R66 = MCD-00058: Resistor, 20R, 0402, +/-1%, 1/16W; BMS_Part_Number: 9131027; Part_Preference: Recommended; Manufacturer: YAGEO; Manufacturer_Part_Number: RC0402FR-0720RL; Component_Country_Of_Origin: China; ID: 2537; ShowFields: YES
R67 = MCD-00052: Resistor, 0R, 0402, +/-5%, 1/16W; Manufacturer_Part_Number: RC0402JR-070RL; Manufacturer: YAGEO; Part_Preference: Recommended; Order_Code_RS: 618-5804; Component_Country_Of_Origin: China; ShowFields: YES; ID: 2540
R267 R269 R286 = MCD-00052: as R46 on sheet Power_PMIC
TP2000 = MCD-00713: Vero Technologies 1.02mm Black Terminal Post; Part_Type: Misc; Manufacturer_Part_Number: 20-2137; Part_Preference: Recommended; Order_Code_RS: 101-2391; Provided_By: SUBCO; Component_Country_Of_Origin: United Kingdom; ID: 3032; ShowFields: YES
U1 = MCD-03375: MPU , 2xCortex-A35@1.5GHz, Cortex-M33@400MHz, TFBGA 14x14, pitch 0.5, 648KB SRAM, With Crypto; Part_Type: IC; Part_Preference: Recommended; Manufacturer: STMICROELECTRONICS; Component_Country_Of_Origin: Unknown; ShowFields: YES; ID: 5491

## Sheet LVDS.SchDoc: LVDS
size A3; Date: Not used; ApprovedBy: Not used; CheckedBy: Not used; Author: Not used; CompanyName: STMicroelectronics; DrawnBy: Not used; Engineer: Not used; Organization: Not used; Address1: Not used; Address2: Not used; Address3: Not used; Address4: Not used; DocumentNumber: Not used; Revision: Not used; SheetNumber: 9; SheetTotal: 18
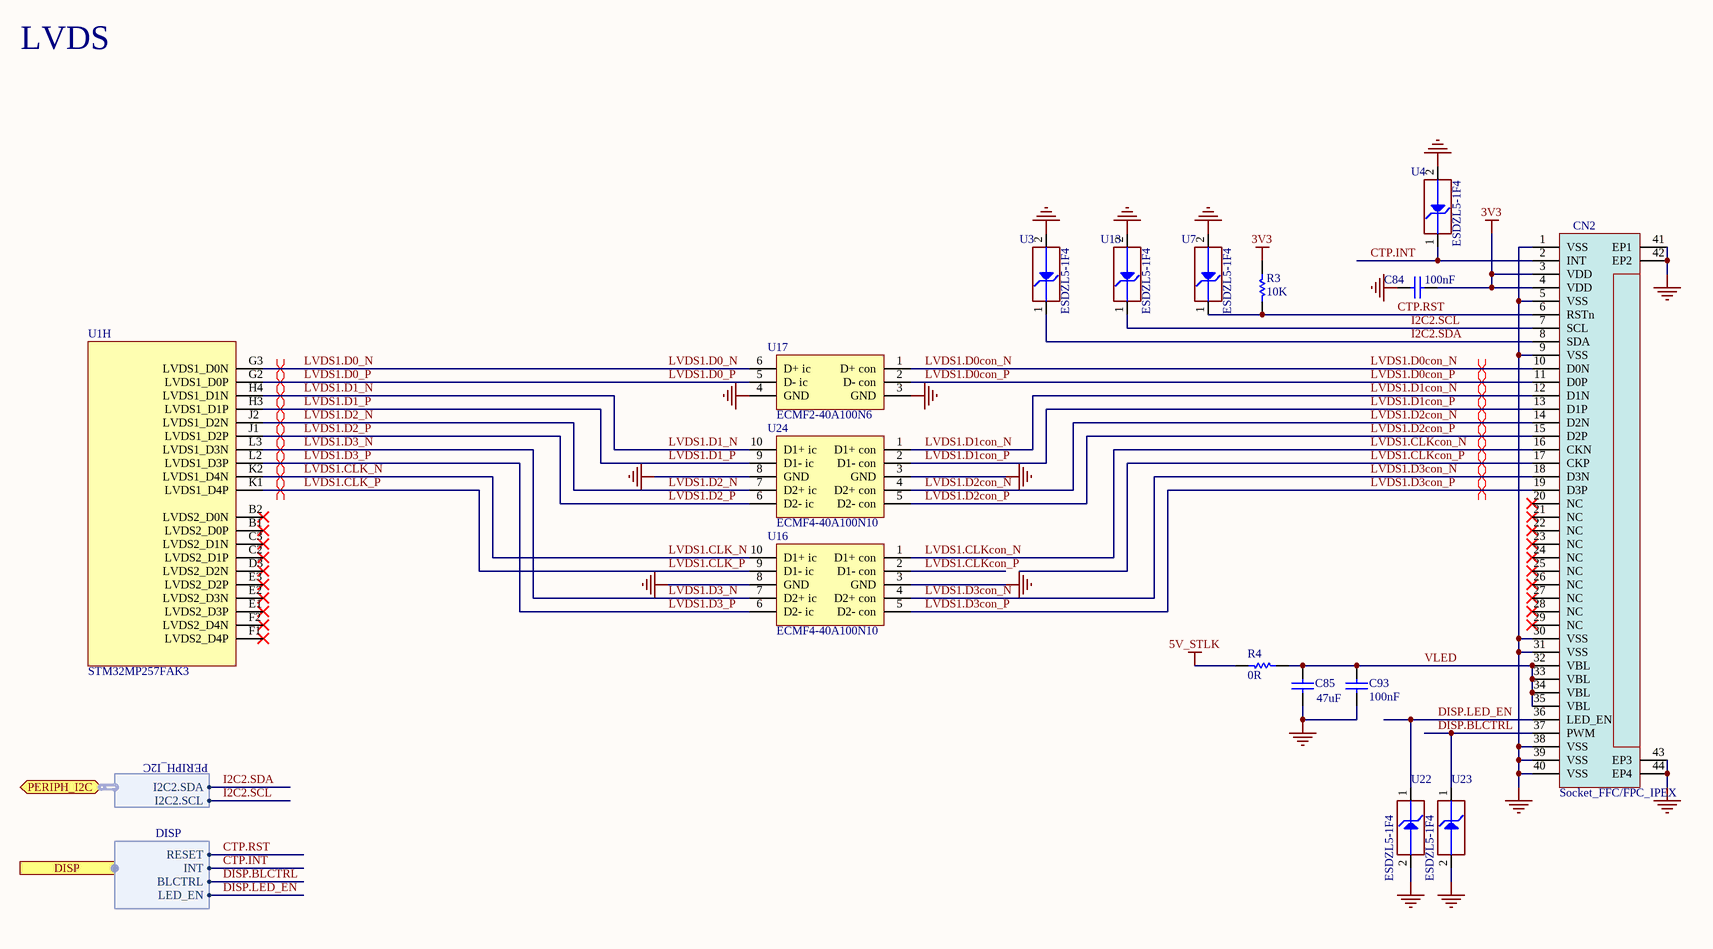
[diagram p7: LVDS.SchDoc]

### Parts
C84  value 100nF  [C0402]  (hidden comment: Capacitor)
C85  value 47uF  [C0805]  (hidden comment: Capacitor)
C93  value 100nF  [C0402]  (hidden comment: Capacitor)
CN2  value Socket_FFC/FPC_IPEX  [CON_I-PEX_20455-040E-76]  (hidden comment: IPEX20455)
R3  value 10K  [R0402]  (hidden comment: Resistor)
R4  value 0R  [R0805]  (hidden comment: Resistor)
U1  STM32MP257FAK3  [ICC_TFBGA424_14X14_P050_H1P20_CODE-B0A2]  (part H of 9)
U3  value ESDZL5-1F4  [ESD_ST0201]  (hidden comment: ESD-TRANSIL)
U4  value ESDZL5-1F4  [ESD_ST0201]  (hidden comment: ESD-TRANSIL)
U7  value ESDZL5-1F4  [ESD_ST0201]  (hidden comment: ESD-TRANSIL)
U13  value ESDZL5-1F4  [ESD_ST0201]  (hidden comment: ESD-TRANSIL)
U16  ECMF4-40A100N10  [ESD_UQFN-10L_2P25X1P4_P040]
U17  ECMF2-40A100N6  [ESD_UQFN-6L_1P45X1P4_P040]
U22  value ESDZL5-1F4  [ESD_ST0201]  (hidden comment: ESD-TRANSIL)
U23  value ESDZL5-1F4  [ESD_ST0201]  (hidden comment: ESD-TRANSIL)
U24  ECMF4-40A100N10  [ESD_UQFN-10L_2P25X1P4_P040]

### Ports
DISP (harness DISP), PERIPH_I2C (bidir, harness PERIPH_I2C)

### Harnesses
DISP: RESET, INT, BLCTRL, LED_EN
PERIPH_I2C: I2C2.SDA, I2C2.SCL

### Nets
3V3: C84.2 CN2.3(VDD) CN2.4(VDD) R3.1
5V_STLK: R4.2
GND: C84.1 C85.1 C93.1 CN2.1(VSS) CN2.5(VSS) CN2.9(VSS) CN2.30(VSS) CN2.31(VSS) CN2.38(VSS) CN2.39(VSS) CN2.40(VSS) CN2.41(EP1) CN2.42(EP2) CN2.43(EP3) CN2.44(EP4) U3.2(GND) U4.2(GND) U7.2(GND) U13.2(GND) U16.3(GND) U16.8(GND) U17.3(GND) U17.4(GND) U22.2(GND) U23.2(GND) U24.3(GND) U24.8(GND)
CTP.INT: CN2.2(INT) U4.1(IO1) ; port DISP.INT
CTP.RST: CN2.6(RSTn) R3.2 U7.1(IO1) ; port DISP.RESET
DISP.BLCTRL: CN2.37(PWM) U23.1(IO1) ; port DISP.BLCTRL
DISP.LED_EN: CN2.36(LED_EN) U22.1(IO1) ; port DISP.LED_EN
I2C2.SCL: CN2.7(SCL) U13.1(IO1) ; port PERIPH_I2C.I2C2.SCL
I2C2.SDA: CN2.8(SDA) U3.1(IO1) ; port PERIPH_I2C.I2C2.SDA
LVDS1.CLK_N: U1.K2(LVDS1_D4N) U16.10(D1+_ic)
LVDS1.CLK_P: U1.K1(LVDS1_D4P) U16.9(D1-_ic)
LVDS1.CLKcon_N: CN2.16(CKN) U16.1(D1+_con)
LVDS1.CLKcon_P: CN2.17(CKP) U16.2(D1-_con)
LVDS1.D0_N: U1.G3(LVDS1_D0N) U17.6(D+_ic)
LVDS1.D0_P: U1.G2(LVDS1_D0P) U17.5(D-_ic)
LVDS1.D0con_N: CN2.10(D0N) U17.1(D+_con)
LVDS1.D0con_P: CN2.11(D0P) U17.2(D-_con)
LVDS1.D1_N: U1.H4(LVDS1_D1N) U24.10(D1+_ic)
LVDS1.D1_P: U1.H3(LVDS1_D1P) U24.9(D1-_ic)
LVDS1.D1con_N: CN2.12(D1N) U24.1(D1+_con)
LVDS1.D1con_P: CN2.13(D1P) U24.2(D1-_con)
LVDS1.D2_N: U1.J2(LVDS1_D2N) U24.7(D2+_ic)
LVDS1.D2_P: U1.J1(LVDS1_D2P) U24.6(D2-_ic)
LVDS1.D2con_N: CN2.14(D2N) U24.4(D2+_con)
LVDS1.D2con_P: CN2.15(D2P) U24.5(D2-_con)
LVDS1.D3_N: U1.L3(LVDS1_D3N) U16.7(D2+_ic)
LVDS1.D3_P: U1.L2(LVDS1_D3P) U16.6(D2-_ic)
LVDS1.D3con_N: CN2.18(D3N) U16.4(D2+_con)
LVDS1.D3con_P: CN2.19(D3P) U16.5(D2-_con)
VLED: C85.2 C93.2 CN2.32(VBL) CN2.33(VBL) CN2.34(VBL) CN2.35(VBL) R4.1

Not connected (* = marked no-connect by the designer): CN2 20(NC)* 21(NC)* 22(NC)* 23(NC)* 24(NC)* 25(NC)* 26(NC)* 27(NC)* 28(NC)* 29(NC)*; U1 B1(LVDS2_D0P)* B2(LVDS2_D0N)* C2(LVDS2_D1P)* C3(LVDS2_D1N)* D3(LVDS2_D2N)* E1(LVDS2_D3P)* E2(LVDS2_D3N)* E3(LVDS2_D2P)* F1(LVDS2_D4P)* F2(LVDS2_D4N)*

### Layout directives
differential pair: LVDS1.CLK_N, LVDS1.CLK_P, LVDS1.CLKcon_N, LVDS1.CLKcon_P, LVDS1.D0_N, LVDS1.D0_P, LVDS1.D0con_N, LVDS1.D0con_P, LVDS1.D1_N, LVDS1.D1_P, LVDS1.D1con_N, LVDS1.D1con_P, LVDS1.D2_N, LVDS1.D2_P, LVDS1.D2con_N, LVDS1.D2con_P, LVDS1.D3_N, LVDS1.D3_P, LVDS1.D3con_N, LVDS1.D3con_P

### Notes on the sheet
- LVDS

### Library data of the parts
C84 C93 = MCD-02352: Capacitor, MLCC, 100nF, 10V, X5R, +/-10%, 0402, T=0,5mm; Part_Preference: Recommended; Manufacturer: YAGEO; Manufacturer_Part_Number: CC0402KRX5R6BB104; Component_Country_Of_Origin: China; ShowFields: YES; ID: 4458
C85 = MCD-00204: Capacitor, MLCC, 47uF, 10V, X5R, +/-20%, 0805, T=1.25mm; Part_Preference: Recommended; Manufacturer: MURATA; Manufacturer_Part_Number: GRM21BR61A476ME15K; Component_Country_Of_Origin: Japan; ShowFields: YES; ID: 2664
CN2 = MCD-03562: Socket_FFC/FPC, 40pins, 0.5mm, RA, SMD, T=1mm; Part_Type: Connector; Part_Preference: Recommended; Manufacturer: I-PEX; Manufacturer_Part_Number: 20455-040E-76; Component_Country_Of_Origin: Singapore; ShowFields: YES; ID: 5678
R3 = MCD-00053: Resistor, 10K, 0402, +/-1%, 1/16W; BMS_Part_Number: 9131590; Part_Preference: Recommended; Manufacturer: YAGEO; Manufacturer_Part_Number: RC0402FR-0710KL; Component_Country_Of_Origin: China; ID: 2539; ShowFields: YES
R4 = MCD-00179: Resistor, 0R, 0805, +/-5%, 1/8W; Part_Preference: Recommended; Manufacturer: YAGEO; Manufacturer_Part_Number: RC0805JR-070RL; Component_Country_Of_Origin: China; ID: 2685; ShowFields: YES
U1 = MCD-03375: as U1 on sheet Power_MPU
U3 U4 U7 U13 U22 U23 = MCD-03501: ESD protection , 0201; Part_Type: IC; Part_Preference: Recommended; Manufacturer: STMICROELECTRONICS; ShowFields: YES; ID: 5617; Order_Code_RS: 163-7318
U16 U24 = MCD-03059: ESD protection & Common Filter High Speed serial Interfaces , 0.4 pitch; Part_Type: IC; Part_Preference: Recommended; Manufacturer: STMICROELECTRONICS; ShowFields: YES; ID: 5175; Component_Country_Of_Origin: China
U17 = MCD-03060: ESD protection & Common Filter High Speed serial Interfaces , 0.4 pitch; Part_Type: IC; Part_Preference: Recommended; Manufacturer: STMICROELECTRONICS; ShowFields: YES; ID: 5176; Component_Country_Of_Origin: China

## Sheet STLINK_V3EC.SchDoc: STLINK-V3EC
size A3; Date: Not used; ApprovedBy: Not used; CheckedBy: Not used; Author: Not used; CompanyName: STMicroelectronics; DrawnBy: Not used; Engineer: Not used; Organization: Not used; Address1: Not used; Address2: Not used; Address3: Not used; Address4: Not used; DocumentNumber: Not used; Revision: V0.1; SheetNumber: 18; SheetTotal: 18
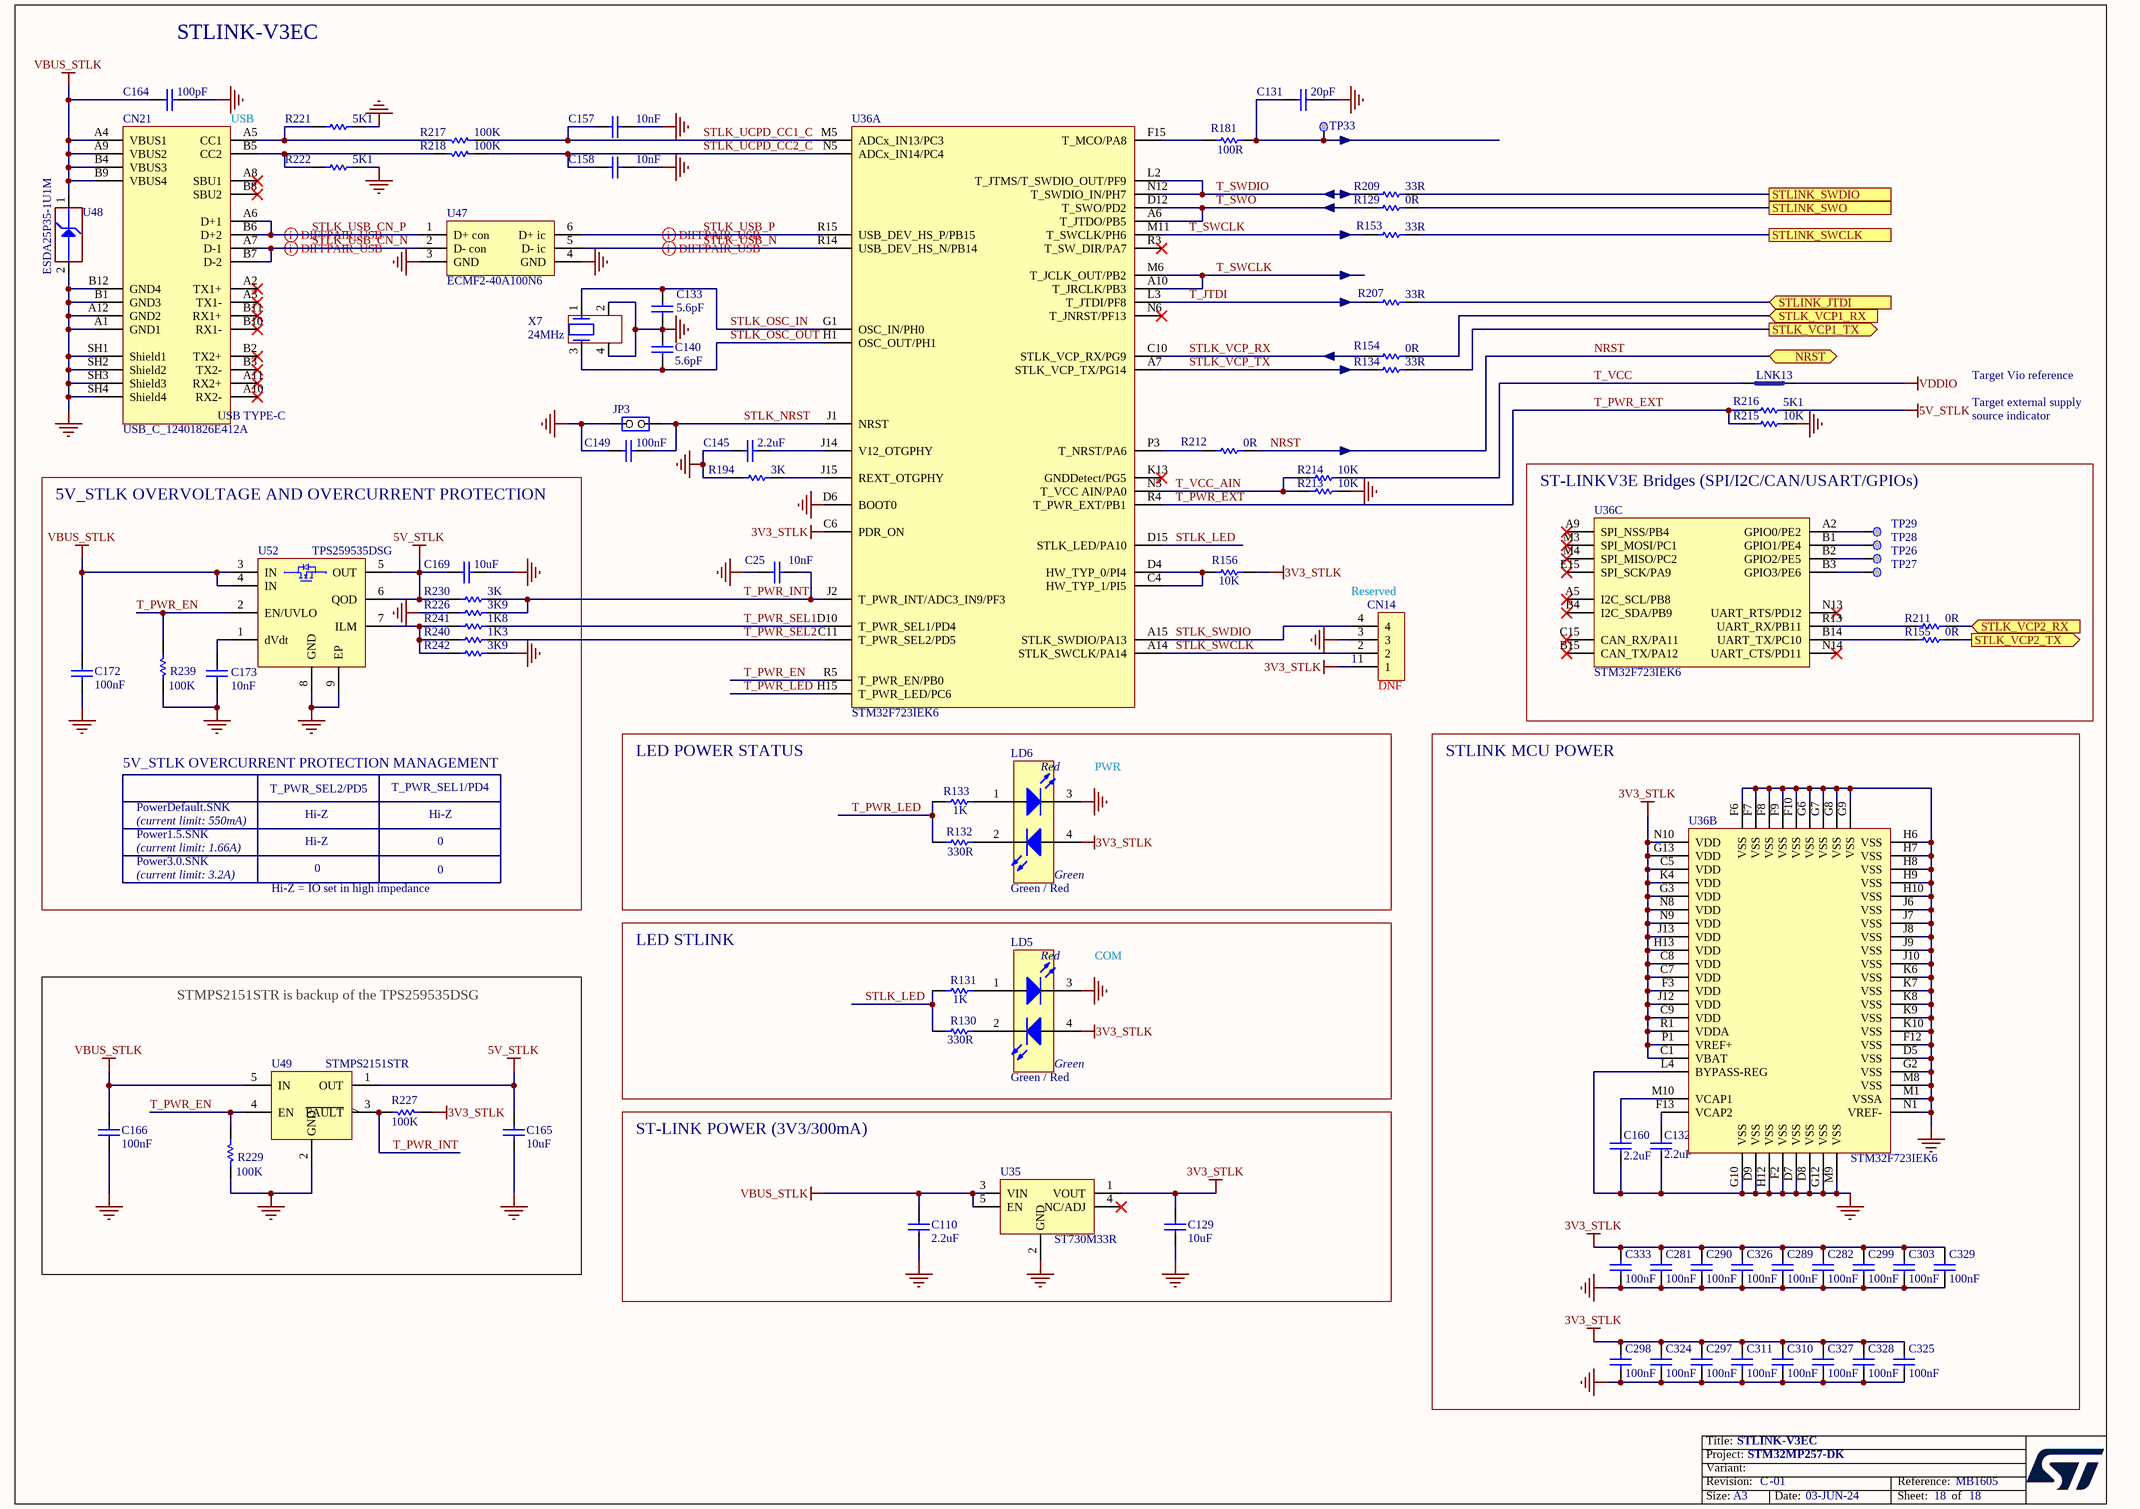
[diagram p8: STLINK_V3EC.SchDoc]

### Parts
C25  value 10nF  [C0402]  (hidden comment: Capacitor)
C110  value 2.2uF  [C0805]  (hidden comment: Capacitor)
C129  value 10uF  [C0603]  (hidden comment: Capacitor)
C131  value 20pF  [C0402]  (hidden comment: Capacitor)
C132  value 2.2uF  [C0402]  (hidden comment: Capacitor)
C133  value 5.6pF  [C0402]  (hidden comment: Capacitor)
C140  value 5.6pF  [C0402]  (hidden comment: Capacitor)
C145  value 2.2uF  [C0402]  (hidden comment: Capacitor)
C149  value 100nF  [C0402]  (hidden comment: Capacitor)
C157  value 10nF  [C0402]  (hidden comment: Capacitor)
C158  value 10nF  [C0402]  (hidden comment: Capacitor)
C160  value 2.2uF  [C0402]  (hidden comment: Capacitor)
C164  value 100pF  [C0402]  (hidden comment: Capacitor)
C165  value 10uF  [C0603]  (hidden comment: Capacitor)
C166  value 100nF  [C0402]  (hidden comment: Capacitor)
C169  value 10uF  [C0603]  (hidden comment: Capacitor)
C172  value 100nF  [C0402]  (hidden comment: Capacitor)
C173  value 10nF  [C0402]  (hidden comment: Capacitor)
C281  value 100nF  [C0402]  (hidden comment: Capacitor)
C282  value 100nF  [C0402]  (hidden comment: Capacitor)
C289  value 100nF  [C0402]  (hidden comment: Capacitor)
C290  value 100nF  [C0402]  (hidden comment: Capacitor)
C297  value 100nF  [C0402]  (hidden comment: Capacitor)
C298  value 100nF  [C0402]  (hidden comment: Capacitor)
C299  value 100nF  [C0402]  (hidden comment: Capacitor)
C303  value 100nF  [C0402]  (hidden comment: Capacitor)
C310  value 100nF  [C0402]  (hidden comment: Capacitor)
C311  value 100nF  [C0402]  (hidden comment: Capacitor)
C324  value 100nF  [C0402]  (hidden comment: Capacitor)
C325  value 100nF  [C0402]  (hidden comment: Capacitor)
C326  value 100nF  [C0402]  (hidden comment: Capacitor)
C327  value 100nF  [C0402]  (hidden comment: Capacitor)
C328  value 100nF  [C0402]  (hidden comment: Capacitor)
C329  value 100nF  [C0402]  (hidden comment: Capacitor)
C333  value 100nF  [C0402]  (hidden comment: Capacitor)
CN14  Header 4x1  [CON_SAMTEC_TSW-104-07-G-S]  (value not drawn)
CN21  value USB_C_12401826E412A  [CON_USB-TYPEC_AMPHENOL_12401826E412A]  (hidden comment: USB_TYPE_C_Receptacle)
JP3  Jumper_Header 2x1  [CON_SAMTEC_TSW-102-07-G-S]  (value not drawn)
LD5  value Green / Red  [LED_BI-GR_WE-150141SV73110]  (hidden comment: LED_BICOLOR)
LD6  value Green / Red  [LED_BI-GR_WE-150141SV73110]  (hidden comment: LED_BICOLOR)
LNK13  link_200  [LINK200]  (value not drawn)  (no BOM)
R129  value 0R  [R0402]  (hidden comment: Resistor)
R130  value 330R  [R0402]  (hidden comment: Resistor)
R131  value 1K  [R0402]  (hidden comment: Resistor)
R132  value 330R  [R0402]  (hidden comment: Resistor)
R133  value 1K  [R0402]  (hidden comment: Resistor)
R134  value 33R  [R0402]  (hidden comment: Resistor)
R153  value 33R  [R0402]  (hidden comment: Resistor)
R154  value 0R  [R0402]  (hidden comment: Resistor)
R155  value 0R  [R0402]  (hidden comment: Resistor)
R156  value 10K  [R0402]  (hidden comment: Resistor)
R181  value 100R  [R0402]  (hidden comment: Resistor)
R194  value 3K  [R0402]  (hidden comment: Resistor)
R207  value 33R  [R0402]  (hidden comment: Resistor)
R209  value 33R  [R0402]  (hidden comment: Resistor)
R211  value 0R  [R0402]  (hidden comment: Resistor)
R212  value 0R  [R0402]  (hidden comment: Resistor)
R213  value 10K  [R0402]  (hidden comment: Resistor)
R214  value 10K  [R0402]  (hidden comment: Resistor)
R215  value 10K  [R0402]  (hidden comment: Resistor)
R216  value 5K1  [R0402]  (hidden comment: Resistor)
R217  value 100K  [R0402]  (hidden comment: Resistor)
R218  value 100K  [R0402]  (hidden comment: Resistor)
R221  value 5K1  [R0402]  (hidden comment: Resistor)
R222  value 5K1  [R0402]  (hidden comment: Resistor)
R226  value 3K9  [R0402]  (hidden comment: Resistor)
R227  value 100K  [R0402]  (hidden comment: Resistor)
R229  value 100K  [R0402]  (hidden comment: Resistor)
R230  value 3K  [R0402]  (hidden comment: Resistor)
R239  value 100K  [R0402]  (hidden comment: Resistor)
R240  value 1K3  [R0402]  (hidden comment: Resistor)
R241  value 1K8  [R0402]  (hidden comment: Resistor)
R242  value 3K9  [R0402]  (hidden comment: Resistor)
TP26  Test Point  [TP_SMD_1MM]  (value not drawn)  (no BOM)
TP27  Test Point  [TP_SMD_1MM]  (value not drawn)  (no BOM)
TP28  Test Point  [TP_SMD_1MM]  (value not drawn)  (no BOM)
TP29  Test Point  [TP_SMD_1MM]  (value not drawn)  (no BOM)
TP33  Test Point  [TP_SMD_1MM]  (value not drawn)  (no BOM)
U35  ST730M33R  [ICC_SOT23-5L_H1P45]
U36  value STM32F723IEK6  [ICC_UFBGA201_176+25_10X10_P065]  (hidden comment: STLINK-V3EC)  (parts A,B,C of 3)
U47  ECMF2-40A100N6  [ESD_UQFN-6L_1P45X1P4_P040]
U48  value ESDA25P35-1U1M  [ESD_QFN1610_2N_1K_2A]  (hidden comment: ESD-TRANSIL)
U49  STMPS2151STR  [MOS_SOT23-5L]
U52  TPS259535DSG  [ICC_WSON8-EPAD_2X2_P050]
X7  value 24MHz  [CRY_NX2016SA_4P]  (hidden comment: XTAL_4_PINS)

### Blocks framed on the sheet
5V_STLK OVERVOLTAGE AND OVERCURRENT PROTECTION: C169 C172 C173 R226 R230 R239-R242 U52
ST-LINKV3E Bridges (SPI/I2C/CAN/USART/GPIOs): R155 R211 TP26-TP29 U36
LED POWER STATUS: LD6 R132 R133
STLINK MCU POWER: C132 C160 C281 C282 C289 C290 C297-C299 C303 C310 C311 C324-C329 C333 U36
LED STLINK: LD5 R130 R131
STMPS2151STR is backup of the TPS259535DSG: C165 C166 R227 R229 U49
ST-LINK POWER (3V3/300mA): C110 C129 U35

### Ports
NRST (bidir), STLINK_JTDI (in), STLINK_SWCLK, STLINK_SWDIO, STLINK_SWO, STLK_VCP1_RX (in), STLK_VCP1_TX (out), STLK_VCP2_RX (in), STLK_VCP2_TX (out)

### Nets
3V3_STLK: C129.2 C281.1 C282.1 C289.1 C290.1 C297.1 C298.1 C299.1 C303.1 C310.1 C311.1 C324.1 C325.1 C326.1 C327.1 C328.1 C329.1 C333.1 CN14.1 LD5.4(Green_anode) LD6.4(Green_anode) R156.2 R227.1 U35.1(VOUT) U36.C1(VBAT) U36.C5(VDD) U36.C6(PDR_ON) U36.C7(VDD) U36.C8(VDD) U36.C9(VDD) U36.F3(VDD) U36.G3(VDD) U36.G13(VDD) U36.H13(VDD) U36.J12(VDD) U36.J13(VDD) U36.K4(VDD) U36.N8(VDD) U36.N9(VDD) U36.N10(VDD) U36.P1(VREF+) U36.R1(VDDA)
5V_STLK: C165.2 C169.2 R216.2 R230.1 U49.1(OUT) U52.5(OUT) U52.6(QOD)
GND: C25.1 C110.1 C129.1 C131.1 C132.1 C133.1 C140.2 C145.1 C149.1 C157.2 C158.2 C160.1 C164.2 C165.1 C166.1 C169.1 C172.1 C173.1 C281.2 C282.2 C289.2 C290.2 C297.2 C298.2 C299.2 C303.2 C310.2 C311.2 C324.2 C325.2 C326.2 C327.2 C328.2 C329.2 C333.2 CN14.3 CN21.A1(GND1) CN21.A12(GND2) CN21.B1(GND3) CN21.B12(GND4) CN21.SH1(Shield1) CN21.SH2(Shield2) CN21.SH3(Shield3) CN21.SH4(Shield4) JP3.2(NO) LD5.3(RED_cathode) LD6.3(RED_cathode) R194.2 R213.2 R215.2 R221.2 R222.2 R226.1 R229.1 R239.1 R242.2 U35.2(GND) U36.D5(VSS) U36.D6(BOOT0) U36.D7(VSS) U36.D8(VSS) U36.D9(VSS) U36.F2(VSS) U36.F6(VSS) U36.F7(VSS) U36.F8(VSS) U36.F9(VSS) U36.F10(VSS) U36.F12(VSS) U36.G2(VSS) U36.G6(VSS) U36.G7(VSS) U36.G8(VSS) U36.G9(VSS) U36.G10(VSS) U36.G12(VSS) U36.H6(VSS) U36.H7(VSS) U36.H8(VSS) U36.H9(VSS) U36.H10(VSS) U36.H12(VSS) U36.J6(VSS) U36.J7(VSS) U36.J8(VSS) U36.J9(VSS) U36.J10(VSS) U36.K6(VSS) U36.K7(VSS) U36.K8(VSS) U36.K9(VSS) U36.K10(VSS) U36.L4(BYPASS-REG) U36.M1(VSSA) U36.M8(VSS) U36.M9(VSS) U36.N1(VREF-) U47.3(GND) U47.4(GND) U48.2(GND) U49.2(GND) U52.8(GND) U52.9(EP) X7.2 X7.4
VBUS_STLK: C110.2 C164.1 C166.2 C172.2 CN21.A4(VBUS1) CN21.A9(VBUS2) CN21.B4(VBUS3) CN21.B9(VBUS4) U35.3(VIN) U35.5(EN) U48.1(IO1) U49.5(IN) U52.3(IN) U52.4(IN)
VDDIO: LNK13.1
JTCK_SWCLK: R153.2 ; port STLINK_SWCLK
JTDI: R207.2 ; port STLINK_JTDI
JTDO_SWDO: R129.2 ; port STLINK_SWO
JTMS_SWDIO: R209.2 ; port STLINK_SWDIO
NRST: R212.2 ; port NRST
STLK_LED: R130.1 R131.2 U36.D15(STLK_LED/PA10)
STLK_NRST: C149.2 JP3.1(COMMON) U36.J1(NRST)
STLK_OSC_IN: C133.2 U36.G1(OSC_IN/PH0) X7.1
STLK_OSC_OUT: C140.1 U36.H1(OSC_OUT/PH1) X7.3
STLK_SWCLK: CN14.2 U36.A14(STLK_SWCLK/PA14)
STLK_SWDIO: CN14.4 U36.A15(STLK_SWDIO/PA13)
STLK_UCPD_CC1_C: C157.1 R217.1 U36.M5(ADCx_IN13/PC3)
STLK_UCPD_CC2_C: C158.1 R218.1 U36.N5(ADCx_IN14/PC4)
STLK_USB_CN_N: CN21.A7(D-1) CN21.B7(D-2) U47.2(D-_con)
STLK_USB_CN_P: CN21.A6(D+1) CN21.B6(D+2) U47.1(D+_con)
STLK_USB_N: U36.R14(USB_DEV_HS_N/PB14) U47.5(D-_ic)
STLK_USB_P: U36.R15(USB_DEV_HS_P/PB15) U47.6(D+_ic)
STLK_VCP1_RX: R154.2 ; port STLK_VCP1_RX
STLK_VCP1_TX: R134.2 ; port STLK_VCP1_TX
STLK_VCP2_RX: R211.1 ; port STLK_VCP2_RX
STLK_VCP2_TX: R155.1 ; port STLK_VCP2_TX
STLK_VCP_RX: R154.1 U36.C10(STLK_VCP_RX/PG9)
STLK_VCP_TX: R134.1 U36.A7(STLK_VCP_TX/PG14)
T_JTDI: R207.1 U36.L3(T_JTDI/PF8)
T_PWR_EN: R229.2 R239.2 U36.R5(T_PWR_EN/PB0) U49.4(EN) U52.2(EN/UVLO)
T_PWR_EXT: R215.1 R216.1 U36.R4(T_PWR_EXT/PB1)
T_PWR_INT: C25.2 R226.2 R227.2 R230.2 U36.J2(T_PWR_INT/ADC3_IN9/PF3) U49.3(~{FAULT})
T_PWR_LED: R132.2 R133.2 U36.H15(T_PWR_LED/PC6)
T_PWR_SEL1: R241.2 U36.D10(T_PWR_SEL1/PD4)
T_PWR_SEL2: R240.2 U36.C11(T_PWR_SEL2/PD5)
T_SWCLK: R153.1 U36.A10(T_JRCLK/PB3) U36.M6(T_JCLK_OUT/PB2) U36.M11(T_SWCLK/PH6)
T_SWDIO: R209.1 U36.L2(T_JTMS/T_SWDIO_OUT/PF9) U36.N12(T_SWDIO_IN/PH7)
T_SWO: R129.1 U36.A6(T_JTDO/PB5) U36.D12(T_SWO/PD2)
T_VCC: LNK13.2 R214.2
T_VCC_AIN: R213.1 R214.1 U36.N3(T_VCC_AIN/PA0)
NetC131_2: C131.2 R181.2 TP33.1
NetC132_2: C132.2 U36.F13(VCAP2)
NetC145_2: C145.2 U36.J14(V12_OTGPHY)
NetC160_2: C160.2 U36.M10(VCAP1)
NetC173_2: C173.2 U52.1(dVdt)
NetCN21_A5: CN21.A5(CC1) R217.2 R221.1
NetCN21_B5: CN21.B5(CC2) R218.2 R222.1
NetLD5_1: LD5.1(Red_anode) R131.1
NetLD5_2: LD5.2(Green_cathode) R130.2
NetLD6_1: LD6.1(Red_anode) R133.1
NetLD6_2: LD6.2(Green_cathode) R132.1
NetR155_2: R155.2 U36.B14(UART_TX/PC10)
NetR156_1: R156.1 U36.C4(HW_TYP_1/PI5) U36.D4(HW_TYP_0/PI4)
NetR181_1: R181.1 U36.F15(T_MCO/PA8)
NetR194_1: R194.1 U36.J15(REXT_OTGPHY)
NetR211_2: R211.2 U36.R13(UART_RX/PB11)
NetR212_1: R212.1 U36.P3(T_NRST/PA6)
NetR240_1: R240.1 R241.1 R242.1 U52.7(ILM)
NetTP26_1: TP26.1 U36.B2(GPIO2/PE5)
NetTP27_1: TP27.1 U36.B3(GPIO3/PE6)
NetTP28_1: TP28.1 U36.B1(GPIO1/PE4)
NetTP29_1: TP29.1 U36.A2(GPIO0/PE2)

Not connected (* = marked no-connect by the designer): CN21 A2(TX1+)* A3(TX1-)* A8(SBU1)* A10(RX2-)* A11(RX2+)* B2(TX2+)* B3(TX2-)* B8(SBU2)* B10(RX1-)* B11(RX1+)*; U35 4(NC/ADJ)*; U36 A5(I2C_SCL/PB8)* A9(SPI_NSS/PB4)* B4(I2C_SDA/PB9)* B15(CAN_TX/PA12)* C15(CAN_RX/PA11)* E15(SPI_SCK/PA9)* K13(GNDDetect/PG5)* M3(SPI_MOSI/PC1)* M4(SPI_MISO/PC2)* N6(T_JNRST/PF13)* N13(UART_RTS/PD12)* N14(UART_CTS/PD11)* R3(T_SW_DIR/PA7)*

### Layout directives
differential pair; rule Impedance Constraint [Min = 85.00    Max = 95.00    ]: STLK_USB_CN_N, STLK_USB_CN_P, STLK_USB_N, STLK_USB_P

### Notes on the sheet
- STLINK-V3EC
- (near CN21) USB
- Target Vio reference
- Target external supply
- source indicator
- (near CN14) Reserved
- (near CN14) 1
- (near CN14) DNF
- 5V_STLK OVERCURRENT PROTECTION MANAGEMENT
- PWR
- (current limit: 550mA)
- (current limit: 1.66A)
- Power1.5.SNK
- PowerDefault.SNK
- T_PWR_SEL2/PD5
- Hi-Z
- T_PWR_SEL1/PD4
- 0
- (current limit: 3.2A)
- Power3.0.SNK
- Hi-Z = IO set in high impedance
- (near LD5) COM

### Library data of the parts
C25 C157 C158 C173 = MCD-02198: Capacitor, MLCC, 10nF, 50V, X7R, +/-10%, 0402, T=0.5mm; Part_Preference: Recommended; Manufacturer: YAGEO; Manufacturer_Part_Number: CC0402KRX7R9BB103; Order_Code_RS: 6169644; Component_Country_Of_Origin: China; ShowFields: YES; ID: 4298
C110 = MCD-02372: Capacitor, MLCC, 2.2uF, 25V, X7R, +/-10%, 0805, T=1,25mm; Manufacturer_Part_Number: GRM21BR71E225KE11L; Manufacturer: MURATA; Part_Preference: Recommended; Component_Country_Of_Origin: Japan; ShowFields: YES; ID: 4478
C129 C169 = MCD-00099: Capacitor, MLCC, 10uF, 10V, X5R, +/-10%, 0603, T=0.8mm; Part_Preference: Recommended; Manufacturer: MURATA; Manufacturer_Part_Number: GRM188R61A106KE69D; Order_Code_RS: 170-6168; Component_Country_Of_Origin: Japan; ShowFields: YES; ID: 2770
C131 = MCD-00016: Capacitor, MLCC, 20pF, 50V, NPO, +/- 5%, 0402, T=0.5mm; Manufacturer_Part_Number: CC0402JRNPO9BN200; Manufacturer: YAGEO; Part_Preference: Recommended; Component_Country_Of_Origin: China; ShowFields: YES; ID: 2479
C132 C145 C160 = MCD-02606: Capacitor, MLCC, 2.2uF, 6.3V, X5R, +/-10%, 0402, T=0.5mm; Part_Preference: Recommended; Manufacturer: YAGEO; Manufacturer_Part_Number: CC0402KRX5R5BB225; Order_Code_RS: 1992205; ShowFields: YES; ID: 4712; Component_Country_Of_Origin: China°
C133 C140 = MCD-01374: Capacitor, MLCC, 5.6pF, 50V, NPO, +/-0.1pF, 0402, T=0.5mm; Part_Preference: Recommended; Manufacturer: YAGEO; Manufacturer_Part_Number: CC0402BRNPO9BN5R6; Component_Country_Of_Origin: China; ShowFields: YES; ID: 3474
C149 C281 C282 C289 C290 C297-C299 C303 C310 C311 C324-C329 C333 = MCD-00006: Capacitor, MLCC, 100nF, 16V, X7R, +/-10%, 0402, T=0.5mm; Manufacturer_Part_Number: CC0402KRX7R7BB104; Manufacturer: YAGEO; Part_Preference: Recommended; Partial_Alternate_Internal_Part_Number: MCD-03299; Order_Code_RS: 616-9701; Component_Country_Of_Origin: China; ShowFields: YES; ID: 2474; Alternate_EMS: M
C164 = MCD-00205: Capacitor, MLCC, 100pF, 50V, NPO, +/-5%, 0402, T=0.5mm; Part_Preference: Recommended; Manufacturer: YAGEO; Manufacturer_Part_Number: CC0402JRNPO9BN101; Component_Country_Of_Origin: China; ShowFields: YES; ID: 2658
C165 = MCD-00099: Capacitor, MLCC, 10uF, 10V, X5R, +/-10%, 0603, T=0.8mm; Part_Preference: Recommended; Manufacturer: MURATA; Manufacturer_Part_Number: GRM188R61A106KE69D; Order_Code_RS: 170-6168; Component_Country_Of_Origin: Japan; ID: 2770; ShowFields: YES
C166 C172 = MCD-02355: Capacitor, MLCC, 100nF, 25V, X7R, +/-10%, 0402, T=0.5mm; Part_Preference: Recommended; Manufacturer: WALSIN; Manufacturer_Part_Number: 0402B104K250CT; Partial_Alternate_Internal_Part_Number: MCD-03302, MCD-03304; Order_Code_RS: 176-3114; Component_Country_Of_Origin: Unknown; ShowFields: YES; ID: 4461; Alternate_EMS: M, M
CN14 = MCD-00029: Header, 4x1, 2.54mm, VR, TH, T=5.84mm/2.54mm; Manufacturer_Part_Number: TSW-104-07-G-S; Manufacturer: SAMTEC; Part_Type: Connector; Part_Preference: Recommended; Order_Code_RS: 161-2261; Component_Country_Of_Origin: China, Costa Rica, Malaysia, United States, Vietnam; ShowFields: YES; ID: 2487
CN21 = MCD-03232: USB_TypeC, 24 pins, RA, SMD, T=2.96mm (USB Certified 3.1); Part_Type: Connector; Part_Preference: Recommended; Manufacturer: AMPHENOL ICC; Manufacturer_Part_Number: 12401826E412A; Component_Country_Of_Origin: China°; ShowFields: YES; ID: 5348
JP3 = MCD-00045: Header, 2x1, 2.54mm, VR, TH, T=5.84mm/2.54mm; Part_Preference: Recommended; Part_Type: Connector; Manufacturer: SAMTEC; Manufacturer_Part_Number: TSW-102-07-G-S; Alternate_Internal_Part_Number: MCD-02390; Order_Code_RS: 155-5312; Component_Country_Of_Origin: China, Costa Rica, Malaysia, United States, Vietnam; ShowFields: YES; ID: 2545
LD5 LD6 = MCD-02631: LED Bicolor, Green/Red, 2V, 20mA,  4-PLCC; Part_Type: Display; Part_Preference: Recommended; Manufacturer: WURTH ELEKTRONIK; Manufacturer_Part_Number: 150141SV73110; Order_Code_RS: 184-6963; Component_Country_Of_Origin: China; ShowFields: YES; ID: 4737
LNK13 = MCD-02777: Track link on PCB 200um width for layout routing. No component assembly and no component in BOM; Part_Type: Misc; Part_Preference: Recommended; ShowFields: YES; ID: 4889
R129 R154 R212 = MCD-00052: Resistor, 0R, 0402, +/-5%, 1/16W; Part_Preference: Recommended; Manufacturer: YAGEO; Manufacturer_Part_Number: RC0402JR-070RL; Order_Code_RS: 618-5804; Component_Country_Of_Origin: China; ShowFields: YES; ID: 2540
R130 R132 = MCD-00062: Resistor, 330R, 0402, +/-1%, 1/16W; Part_Preference: Recommended; Manufacturer: YAGEO; Manufacturer_Part_Number: RC0402FR-07330RL; Component_Country_Of_Origin: China; ShowFields: YES; ID: 2529
R131 R133 = MCD-02665: Resistor, 1K, 0402, +/-0.1%, 1/16W, +/-25ppm/°C; Part_Preference: Recommended; Manufacturer: YAGEO; Manufacturer_Part_Number: RT0402BRD071KL; Order_Code_RS: 199-1298; ShowFields: YES; ID: 4771
R134 R153 R207 R209 = MCD-00455: Resistor, 33R, 0402, +/-1%, 1/16W; Part_Preference: Recommended; Manufacturer: YAGEO; Manufacturer_Part_Number: RC0402FR-0733RL; Component_Country_Of_Origin: China; ShowFields: YES; ID: 2821
R155 R211 = MCD-00052: as R67 on sheet Power_MPU
R156 R213-R215 = MCD-00053: Resistor, 10K, 0402, +/-1%, 1/16W; Manufacturer_Part_Number: RC0402FR-0710KL; Manufacturer: YAGEO; BMS_Part_Number: 9131590; Part_Preference: Recommended; Component_Country_Of_Origin: China; ShowFields: YES; ID: 2539
R181 = MCD-00067: Resistor, 100R, 0402, +/- 1%, 1/16W; Part_Preference: Recommended; Manufacturer: YAGEO; Manufacturer_Part_Number: RC0402FR-07100RL; Component_Country_Of_Origin: China; ShowFields: YES; ID: 2527
R194 = MCD-00185: Resistor, 3K, 0402, +/-1%, 1/16W; Manufacturer_Part_Number: RC0402FR-073KL; Manufacturer: YAGEO; Part_Preference: Recommended; Component_Country_Of_Origin: China; ShowFields: YES; ID: 2682
R216 R221 R222 = MCD-00333: Resistor, 5K1, 0402, +/-1%, 1/16W; Part_Preference: Recommended; Manufacturer: YAGEO; Manufacturer_Part_Number: RC0402FR-075K1L; Component_Country_Of_Origin: China; ShowFields: YES; ID: 2944
R217 R218 R227 R229 R239 = MCD-00059: Resistor, 100K, 0402, +/-1%, 1/16W; Manufacturer_Part_Number: RC0402FR-07100KL; Manufacturer: YAGEO; Part_Preference: Recommended; Partial_Alternate_Internal_Part_Number: MCD-03301; Component_Country_Of_Origin: China; ShowFields: YES; ID: 2533; Alternate_EMS: M
R226 R242 = MCD-02455: Resistor, 3K9, 0402, +/-1%, 1/16W, +/-100ppm/°C; Part_Preference: Recommended; Manufacturer: YAGEO; Manufacturer_Part_Number: RC0402FR-073K9L; Order_Code_RS: 198-7783; Component_Country_Of_Origin: China; ShowFields: YES; ID: 4561
R230 = MCD-00185: Resistor, 3K, 0402, +/-1%, 1/16W; Part_Preference: Recommended; Manufacturer: YAGEO; Manufacturer_Part_Number: RC0402FR-073KL; Component_Country_Of_Origin: China; ShowFields: YES; ID: 2682
R240 = MCD-00381: Resistor, 1K3, 0402, +/-1%, 1/16W; Part_Preference: Recommended; Manufacturer: YAGEO; Manufacturer_Part_Number: RC0402FR-071K3L; Component_Country_Of_Origin: China; ShowFields: YES; ID: 2898
R241 = MCD-00409: Resistor, 1K8, 0402, +/-1%, 1/16W; Part_Preference: Recommended; Manufacturer: YAGEO; Manufacturer_Part_Number: RC0402FR-071K8L; Component_Country_Of_Origin: China; ShowFields: YES; ID: 2871
TP26-TP29 = MCD-00074: Test Point 1mm; Part_Type: Misc; Part_Preference: Recommended; ID: 2518; ShowFields: YES
TP33 = MCD-00074: Test Point 1mm; Part_Type: Misc; Part_Preference: Recommended; ShowFields: YES; ID: 2518
U35 = MCD-02514: LDO, 3.3V, 300mA, High input voltage: 2.5V to 28V, SOT23-5L; Part_Type: IC; Part_Preference: Recommended; Manufacturer: STMICROELECTRONICS; Component_Country_Of_Origin: Malaysia; ShowFields: YES; ID: 4620
U36 = MCD-03851: MCU, ARM Cortex-M7 32-bit, 512KB Flash, 276KB RAM, With Crypto; Part_Type: IC; Part_Preference: Recommended; Manufacturer: STMICROELECTRONICS; Component_Country_Of_Origin: Philippines; ShowFields: YES; ID: 5967
U47 = MCD-03060: IC, ESD protection and Common Filter High Speed serial Interfaces, 10.7 GHz; Part_Preference: Recommended; Manufacturer: STMICROELECTRONICS; Component_Country_Of_Origin: China; ShowFields: YES; ID: 5176
U48 = MCD-01207: High power Transient voltage suppressor:25V/35A EOS and ESD transients protection.; Part_Type: Diode; Manufacturer: STMICROELECTRONICS; BMS_Part_Number: 9179045; Part_Preference: Recommended; Manufacturer_HQ_COO: EU; Component_Country_Of_Origin: China; ShowFields: YES; ID: 3289
U49 = MCD-00159: 500mA, Enhanced single channel power switches with active high enable pin; Part_Type: IC; Manufacturer: STMICROELECTRONICS; Alternate_Manufacturer_Part_Number: TPS2051C; Alternate_Manufacturer: TEXAS INSTRUMENTS; BMS_Part_Number: 9159009; Manufacturer_HQ_COO: EU; Part_Preference: Recommended; Provided_By: Subcon; Initial_Board_Reference: MB1264; Component_Country_Of_Origin: Malaysia; ID: 2708; Order_Code_RS: 880-5415; ShowFields: YES
U52 = MCD-02532: IC, eFuse with Fast Overvoltage Protection 2.7V to 18V 4A 34mOhm 8-Pin WSON; Part_Preference: Recommended; Manufacturer: TEXAS INSTRUMENTS; ShowFields: YES; ID: 4638
X7 = MCD-01036: Crystal, 24MHz, 6pF, +/-20ppm, 80R, 2x1.6mm; BMS_Part_Number: 9157045; Part_Type: Crystal_Osc; Part_Preference: Recommended; Manufacturer: NDK; Manufacturer_Part_Number: NX2016SA-24MHZ-EXS00A-CS10820; Component_Country_Of_Origin: Unknown; ID: 2989; ShowFields: YES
